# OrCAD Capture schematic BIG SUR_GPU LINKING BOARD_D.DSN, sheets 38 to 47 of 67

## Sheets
38 P38  PCIe x16 Slot-7: size C
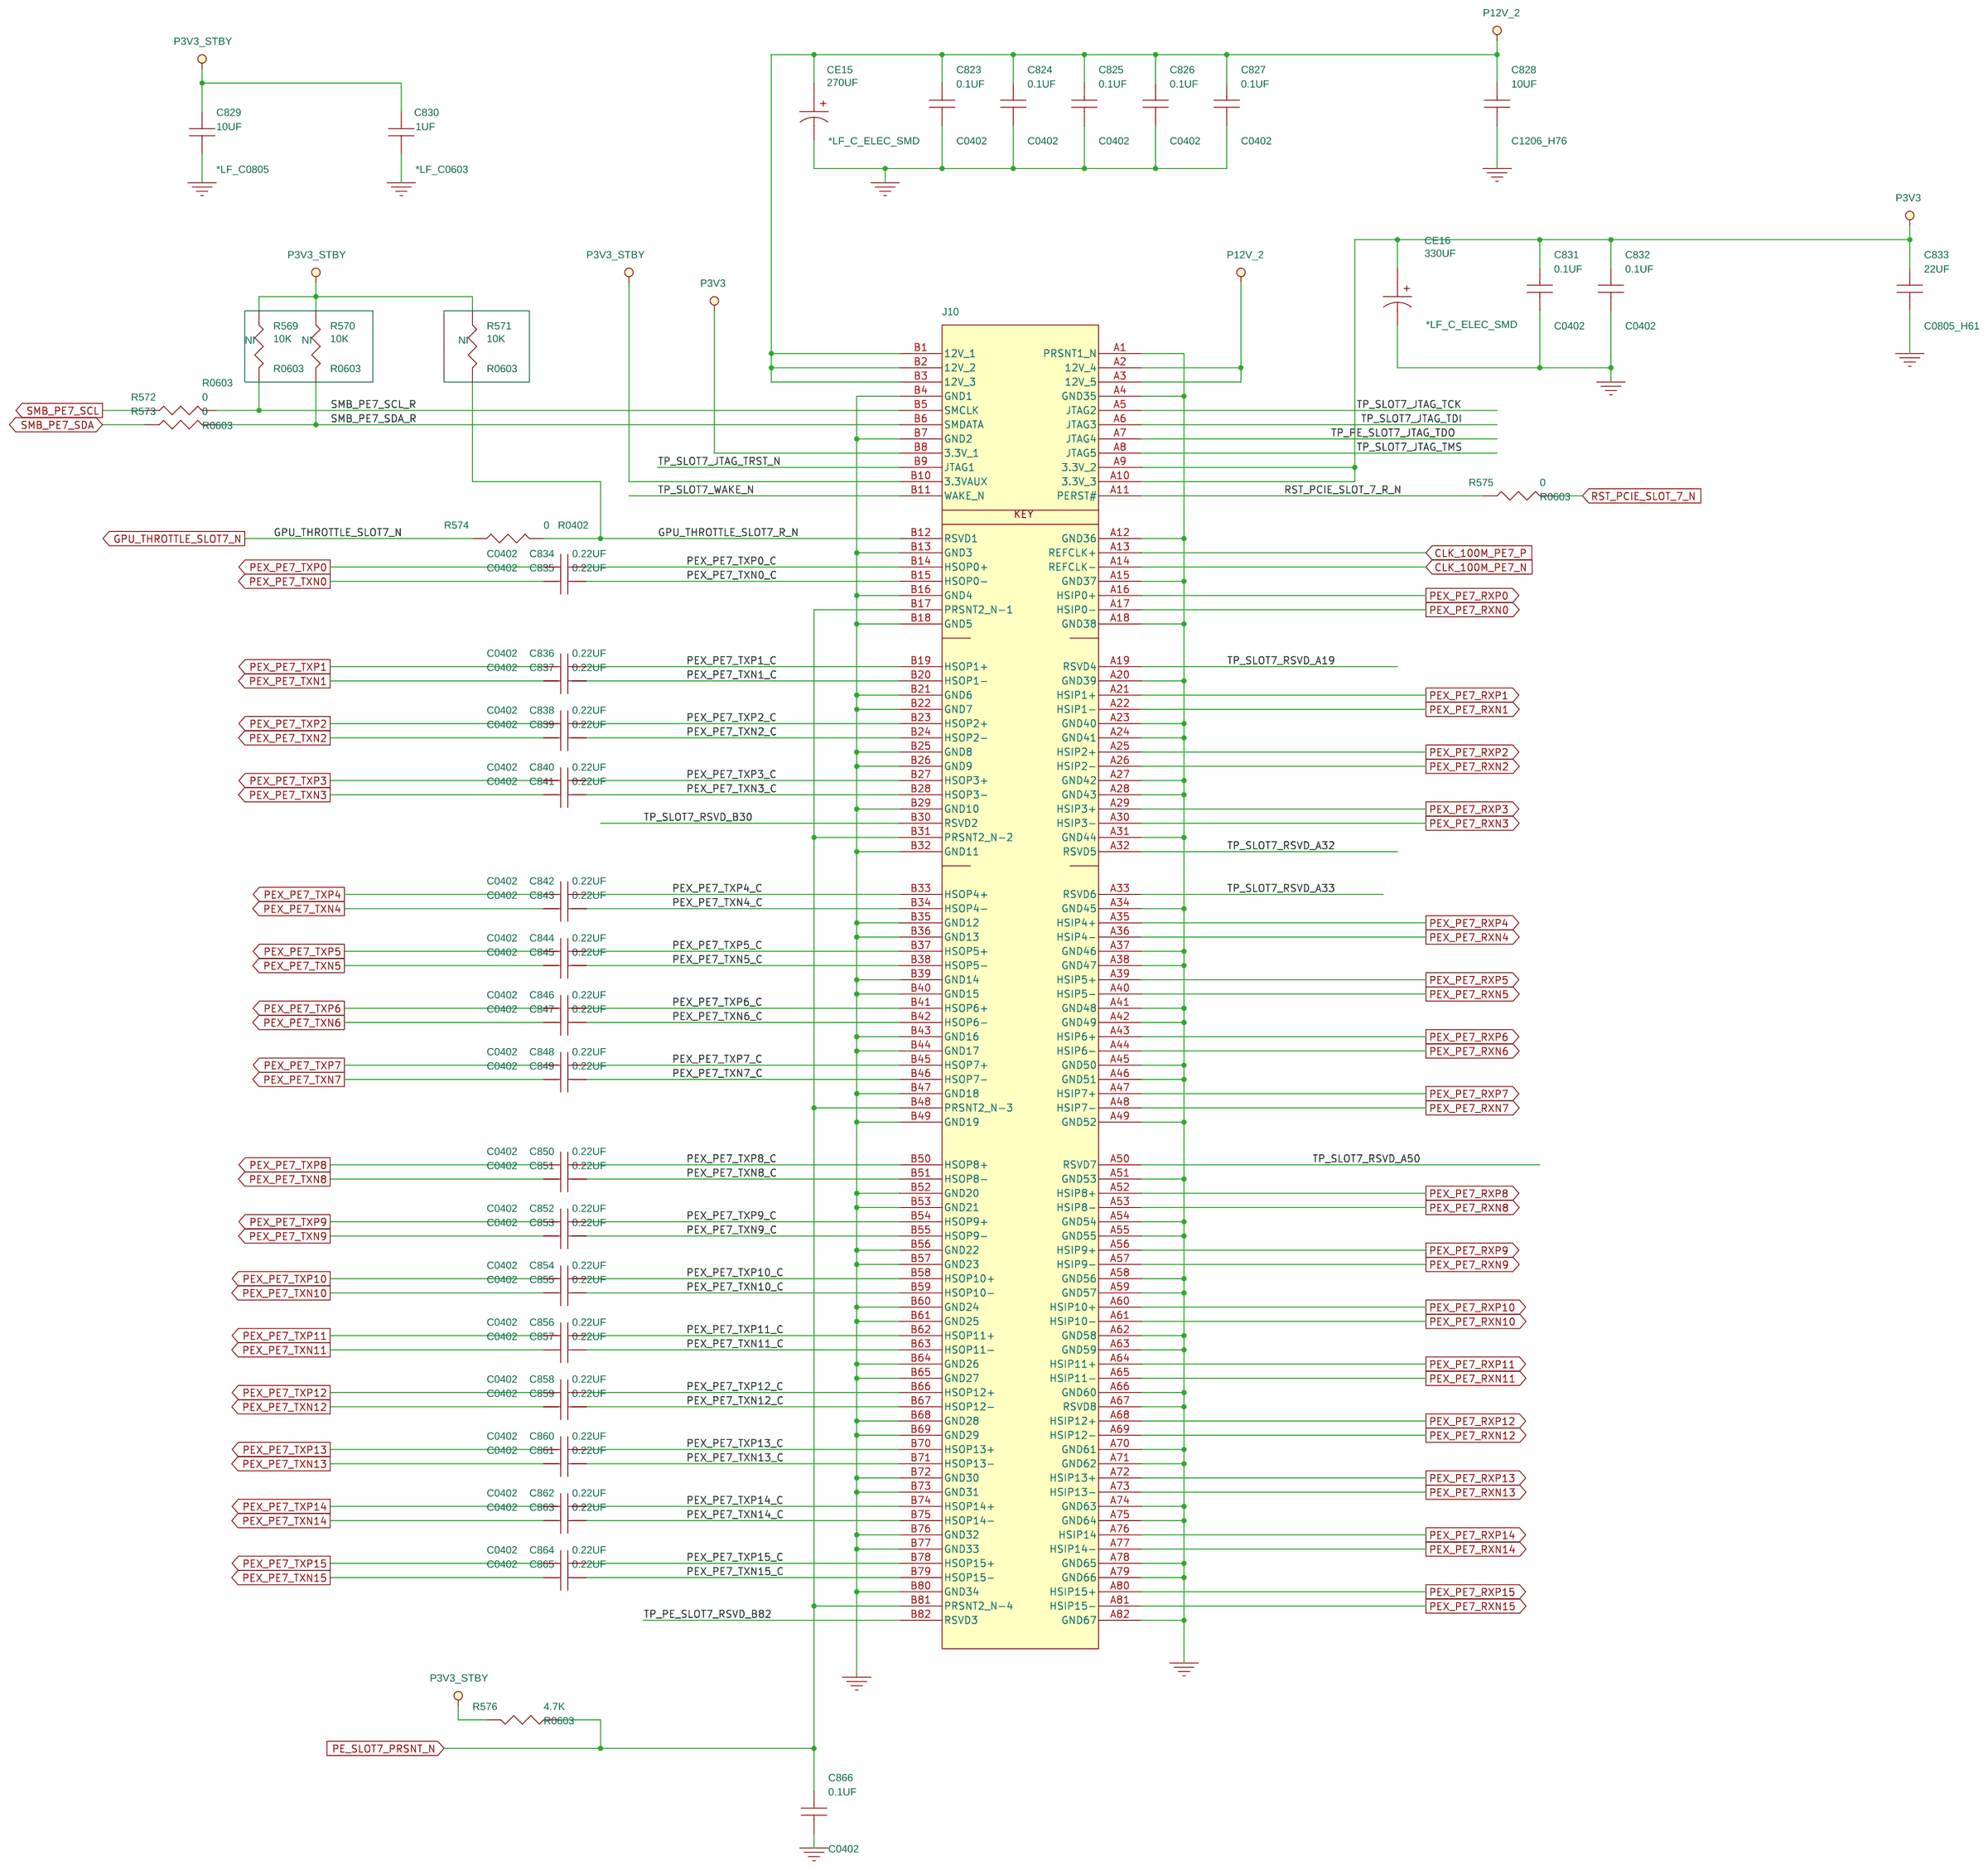
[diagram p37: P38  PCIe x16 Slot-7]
39 P39  MINI SAS HD for NIC 1&2: size C
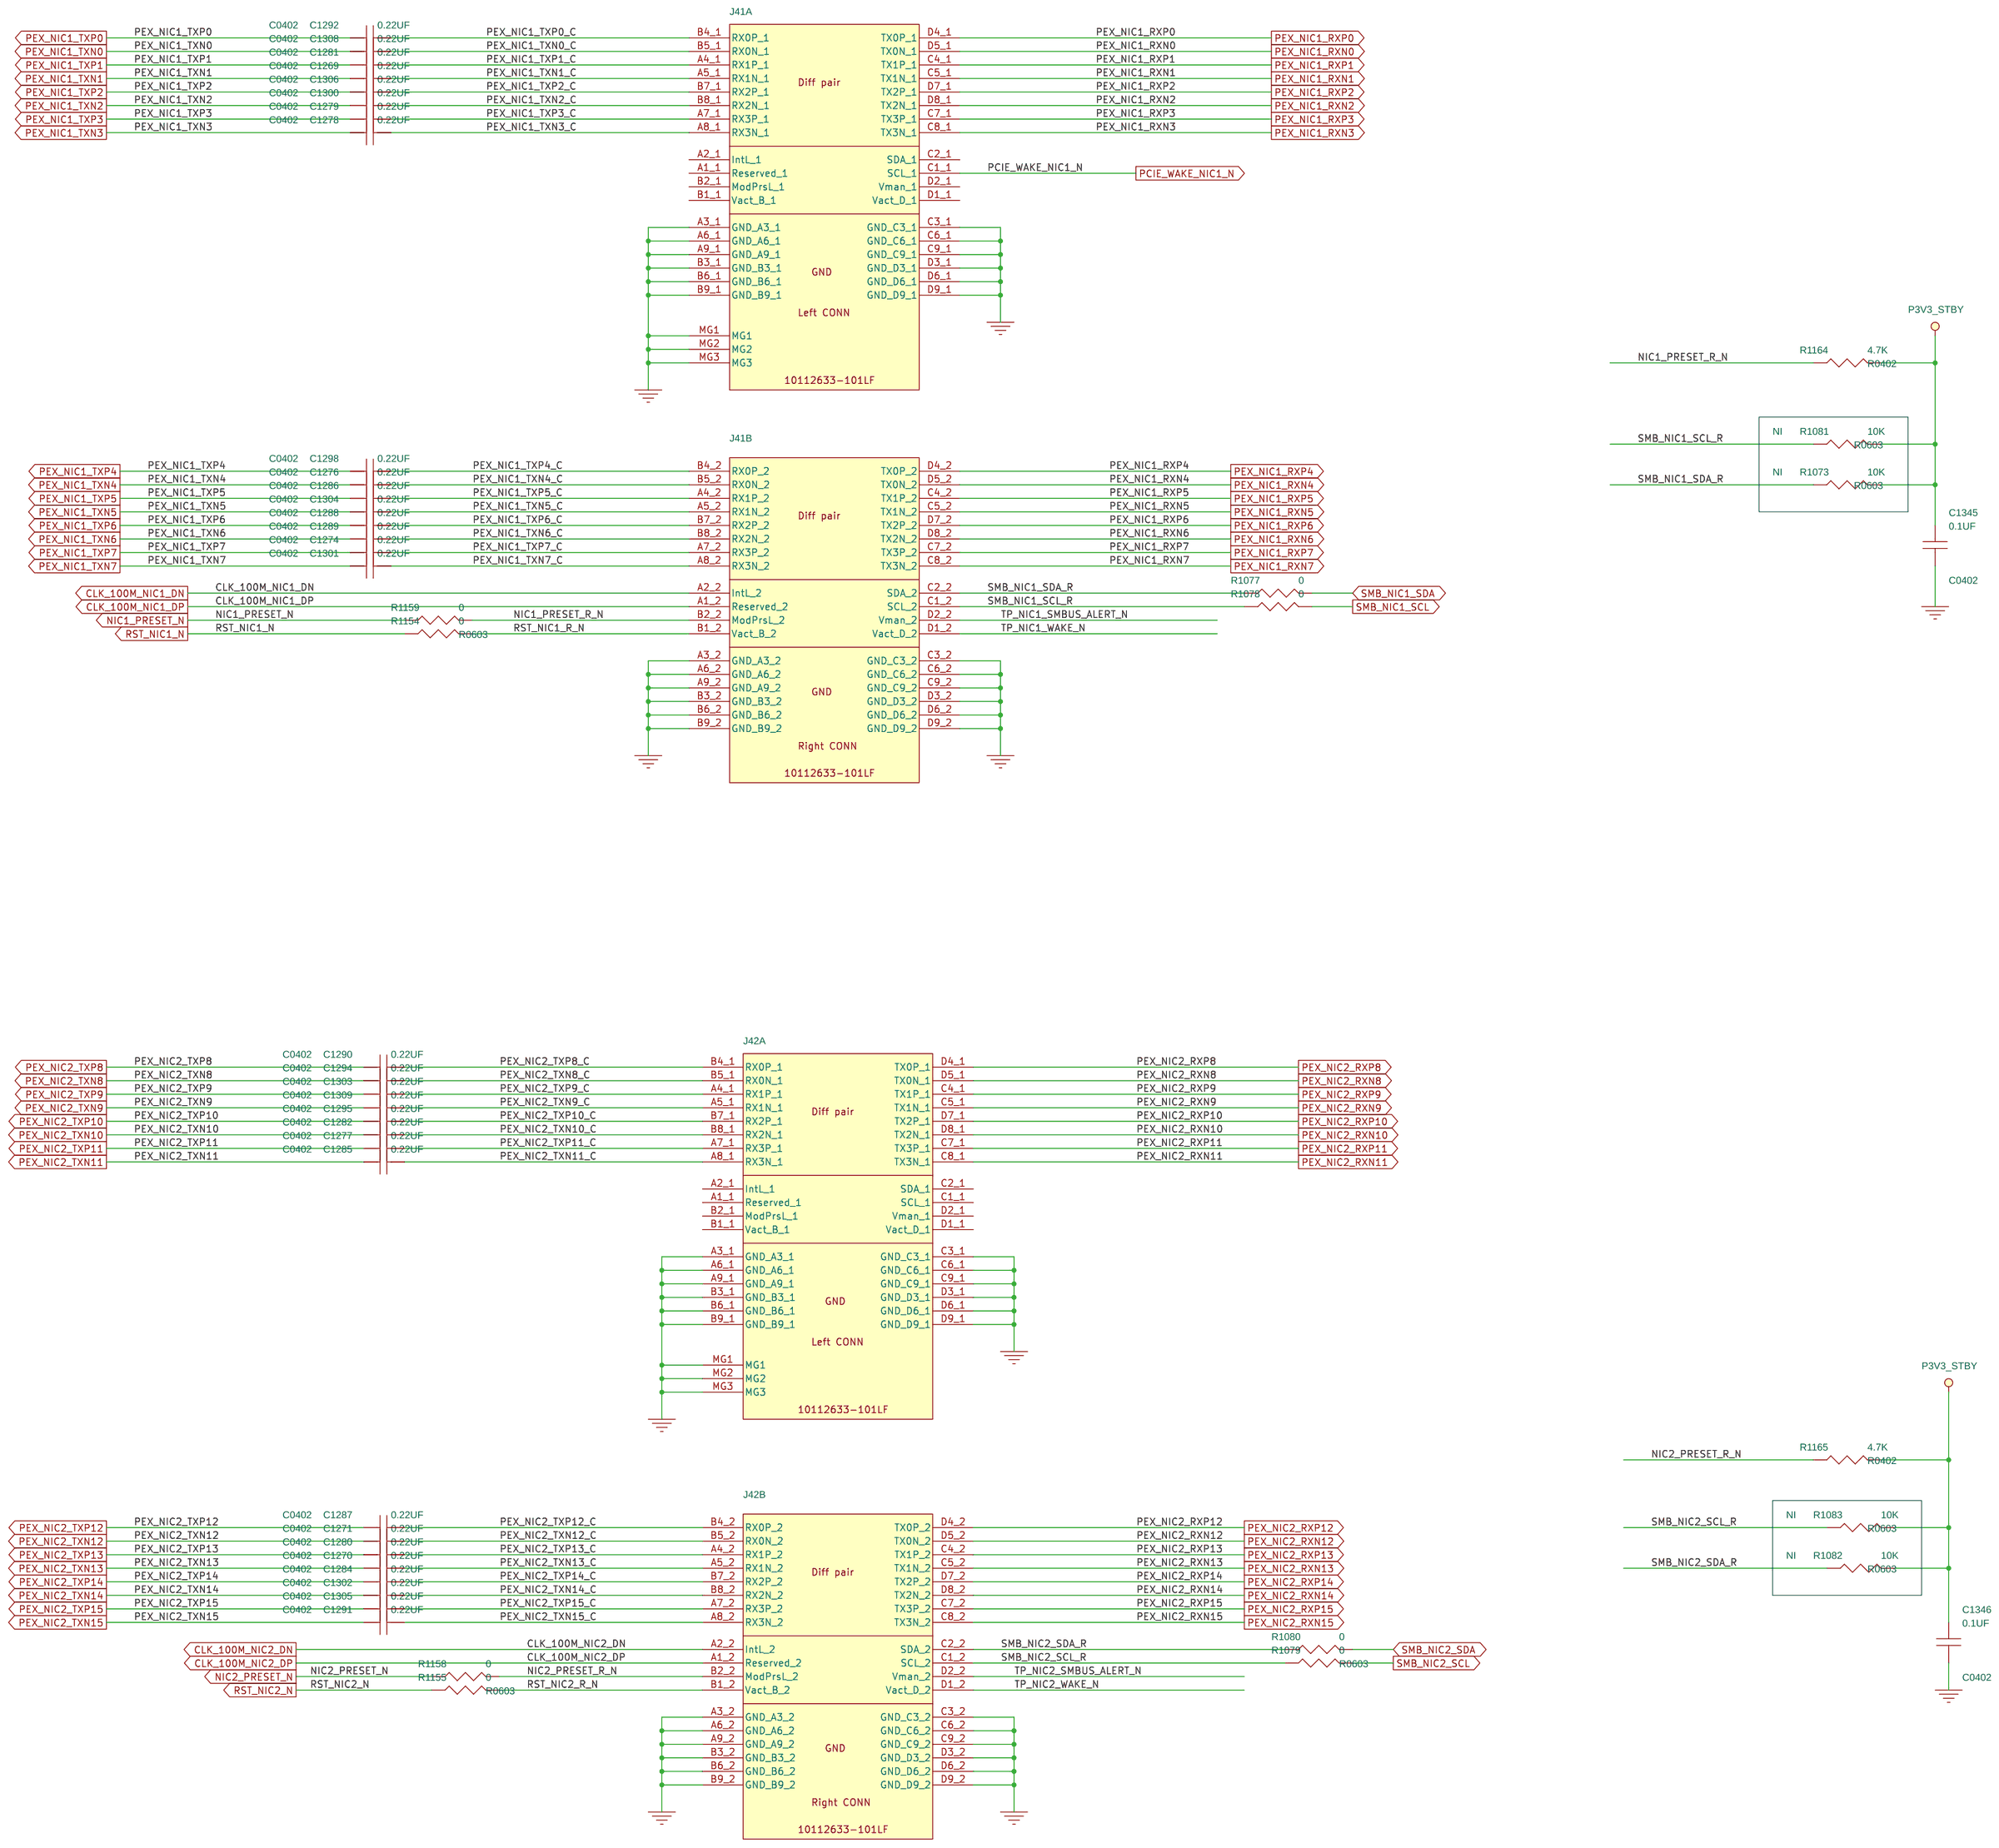
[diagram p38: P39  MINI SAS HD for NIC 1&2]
40 P40  MINI SAS HD for NIC 3&4: size C
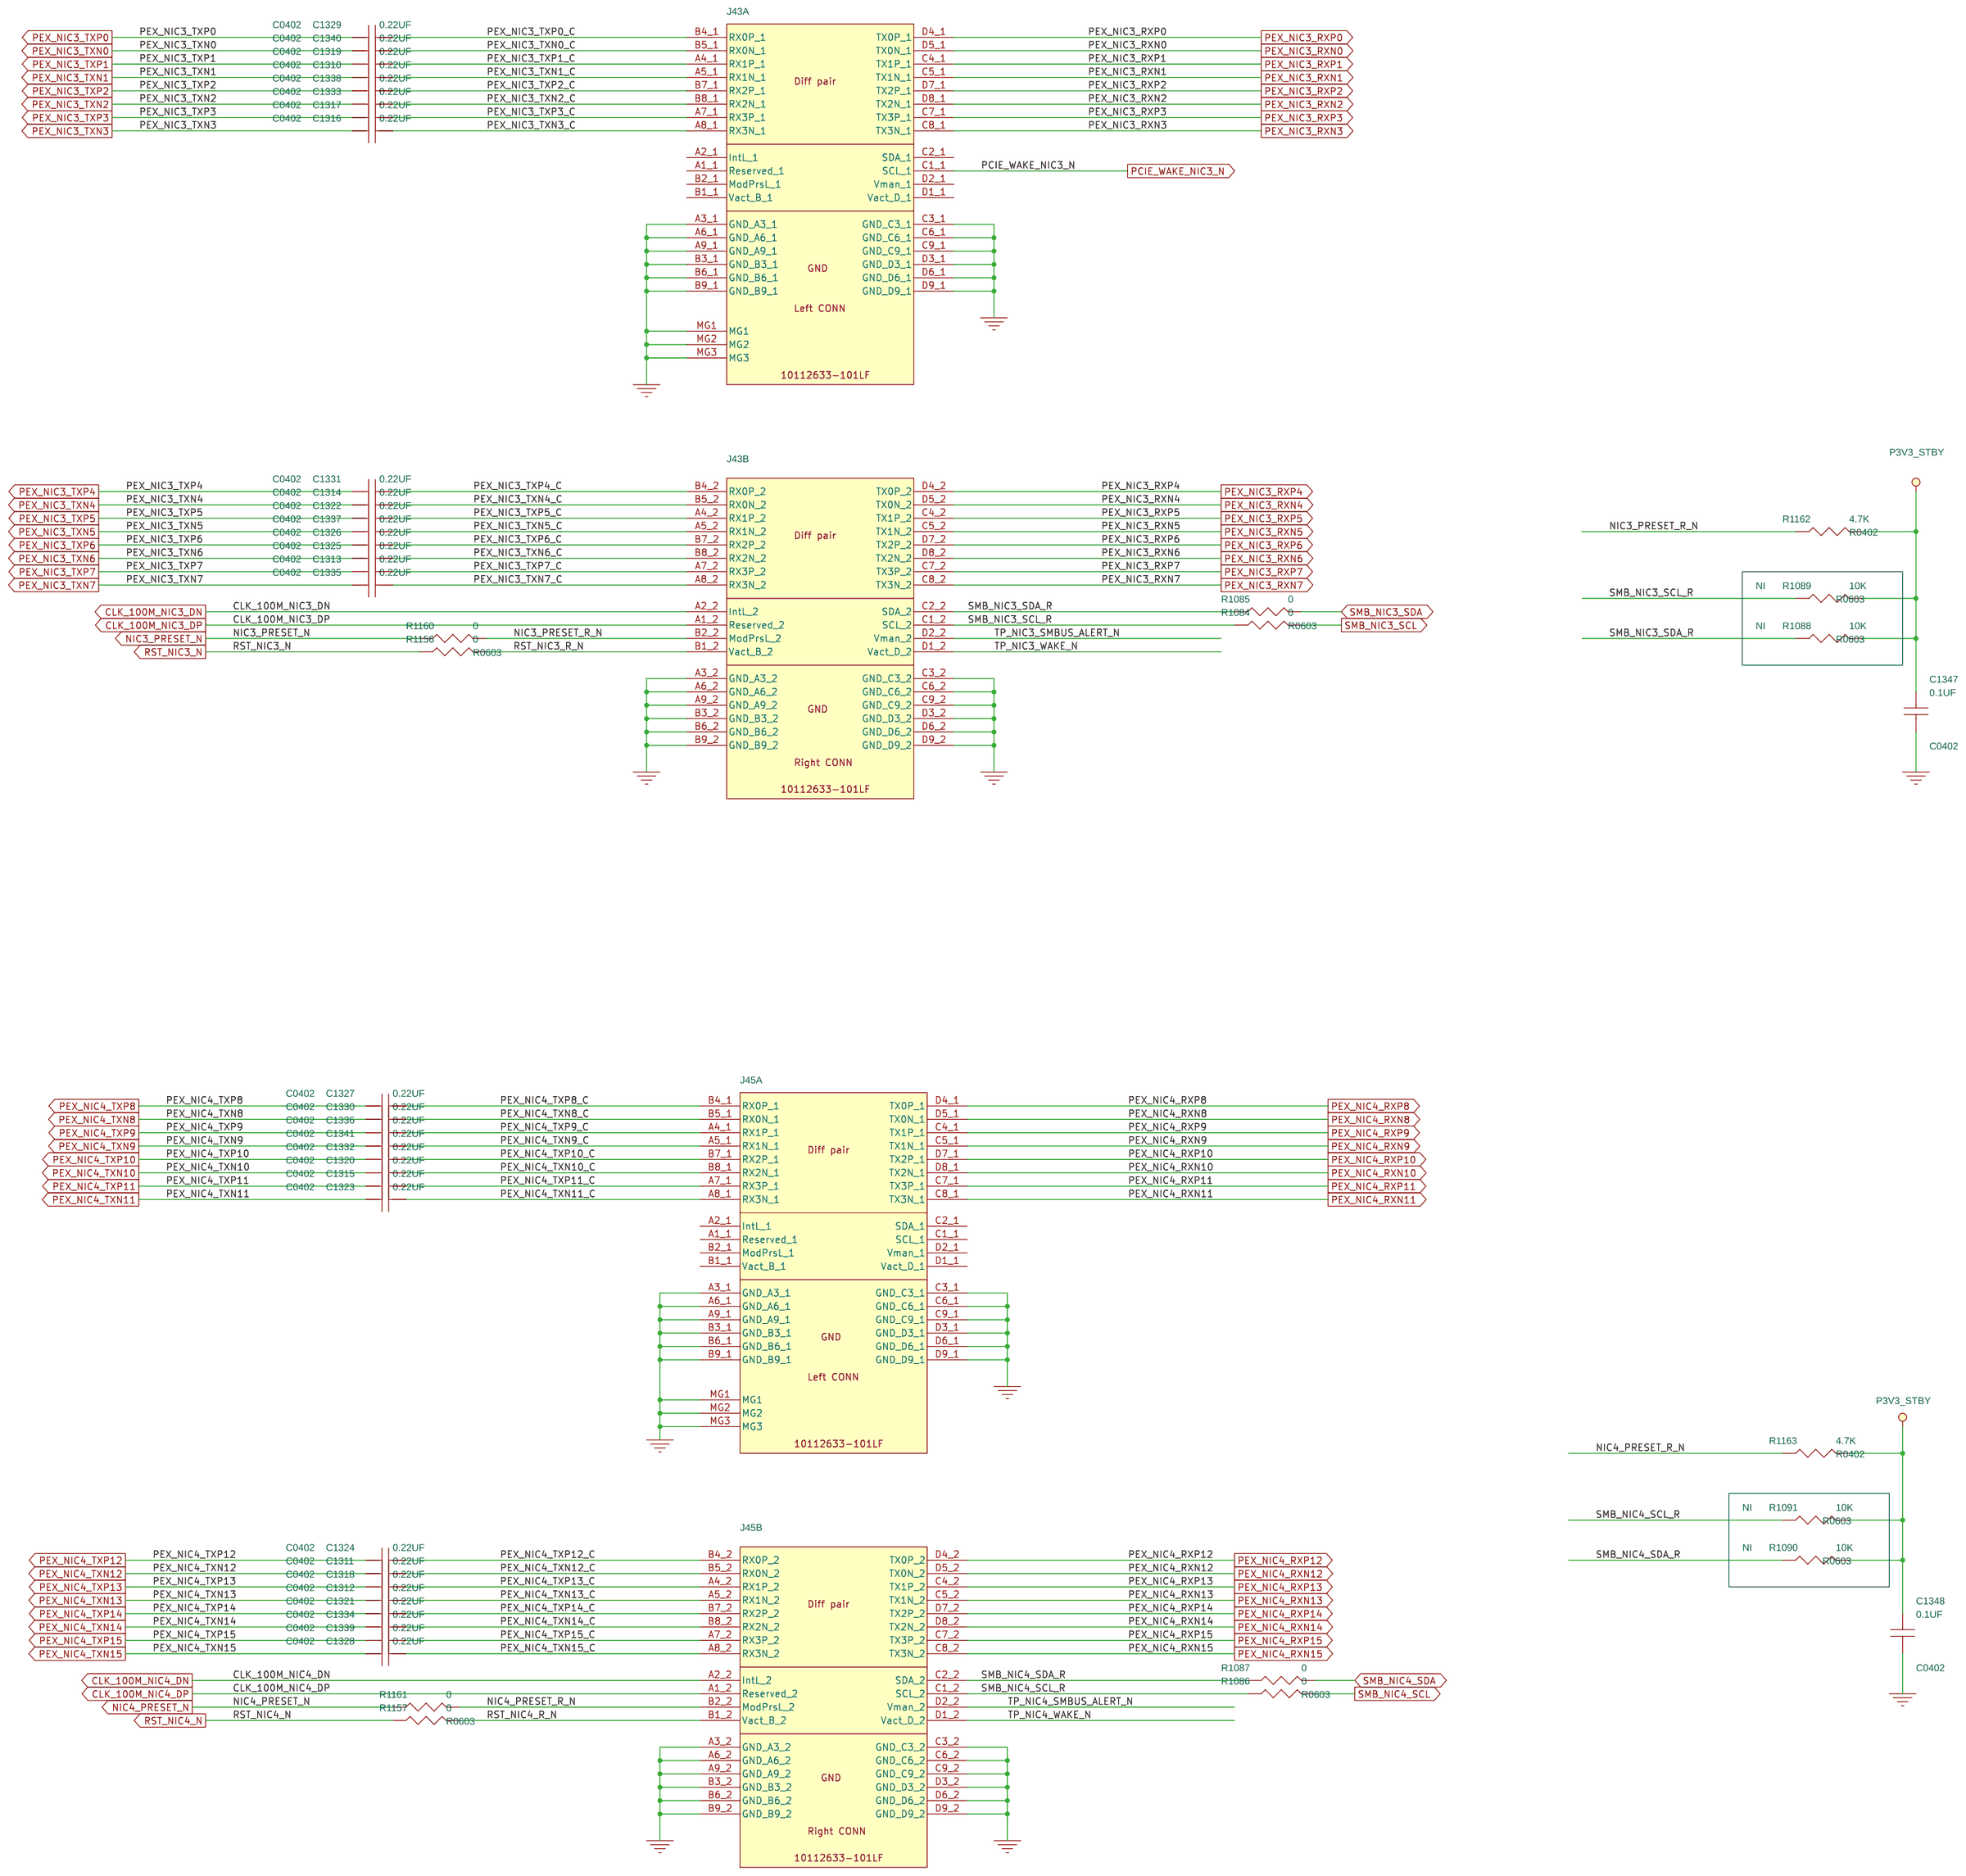
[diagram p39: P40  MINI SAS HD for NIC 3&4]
41 P41  Main Board Power Connector: size C
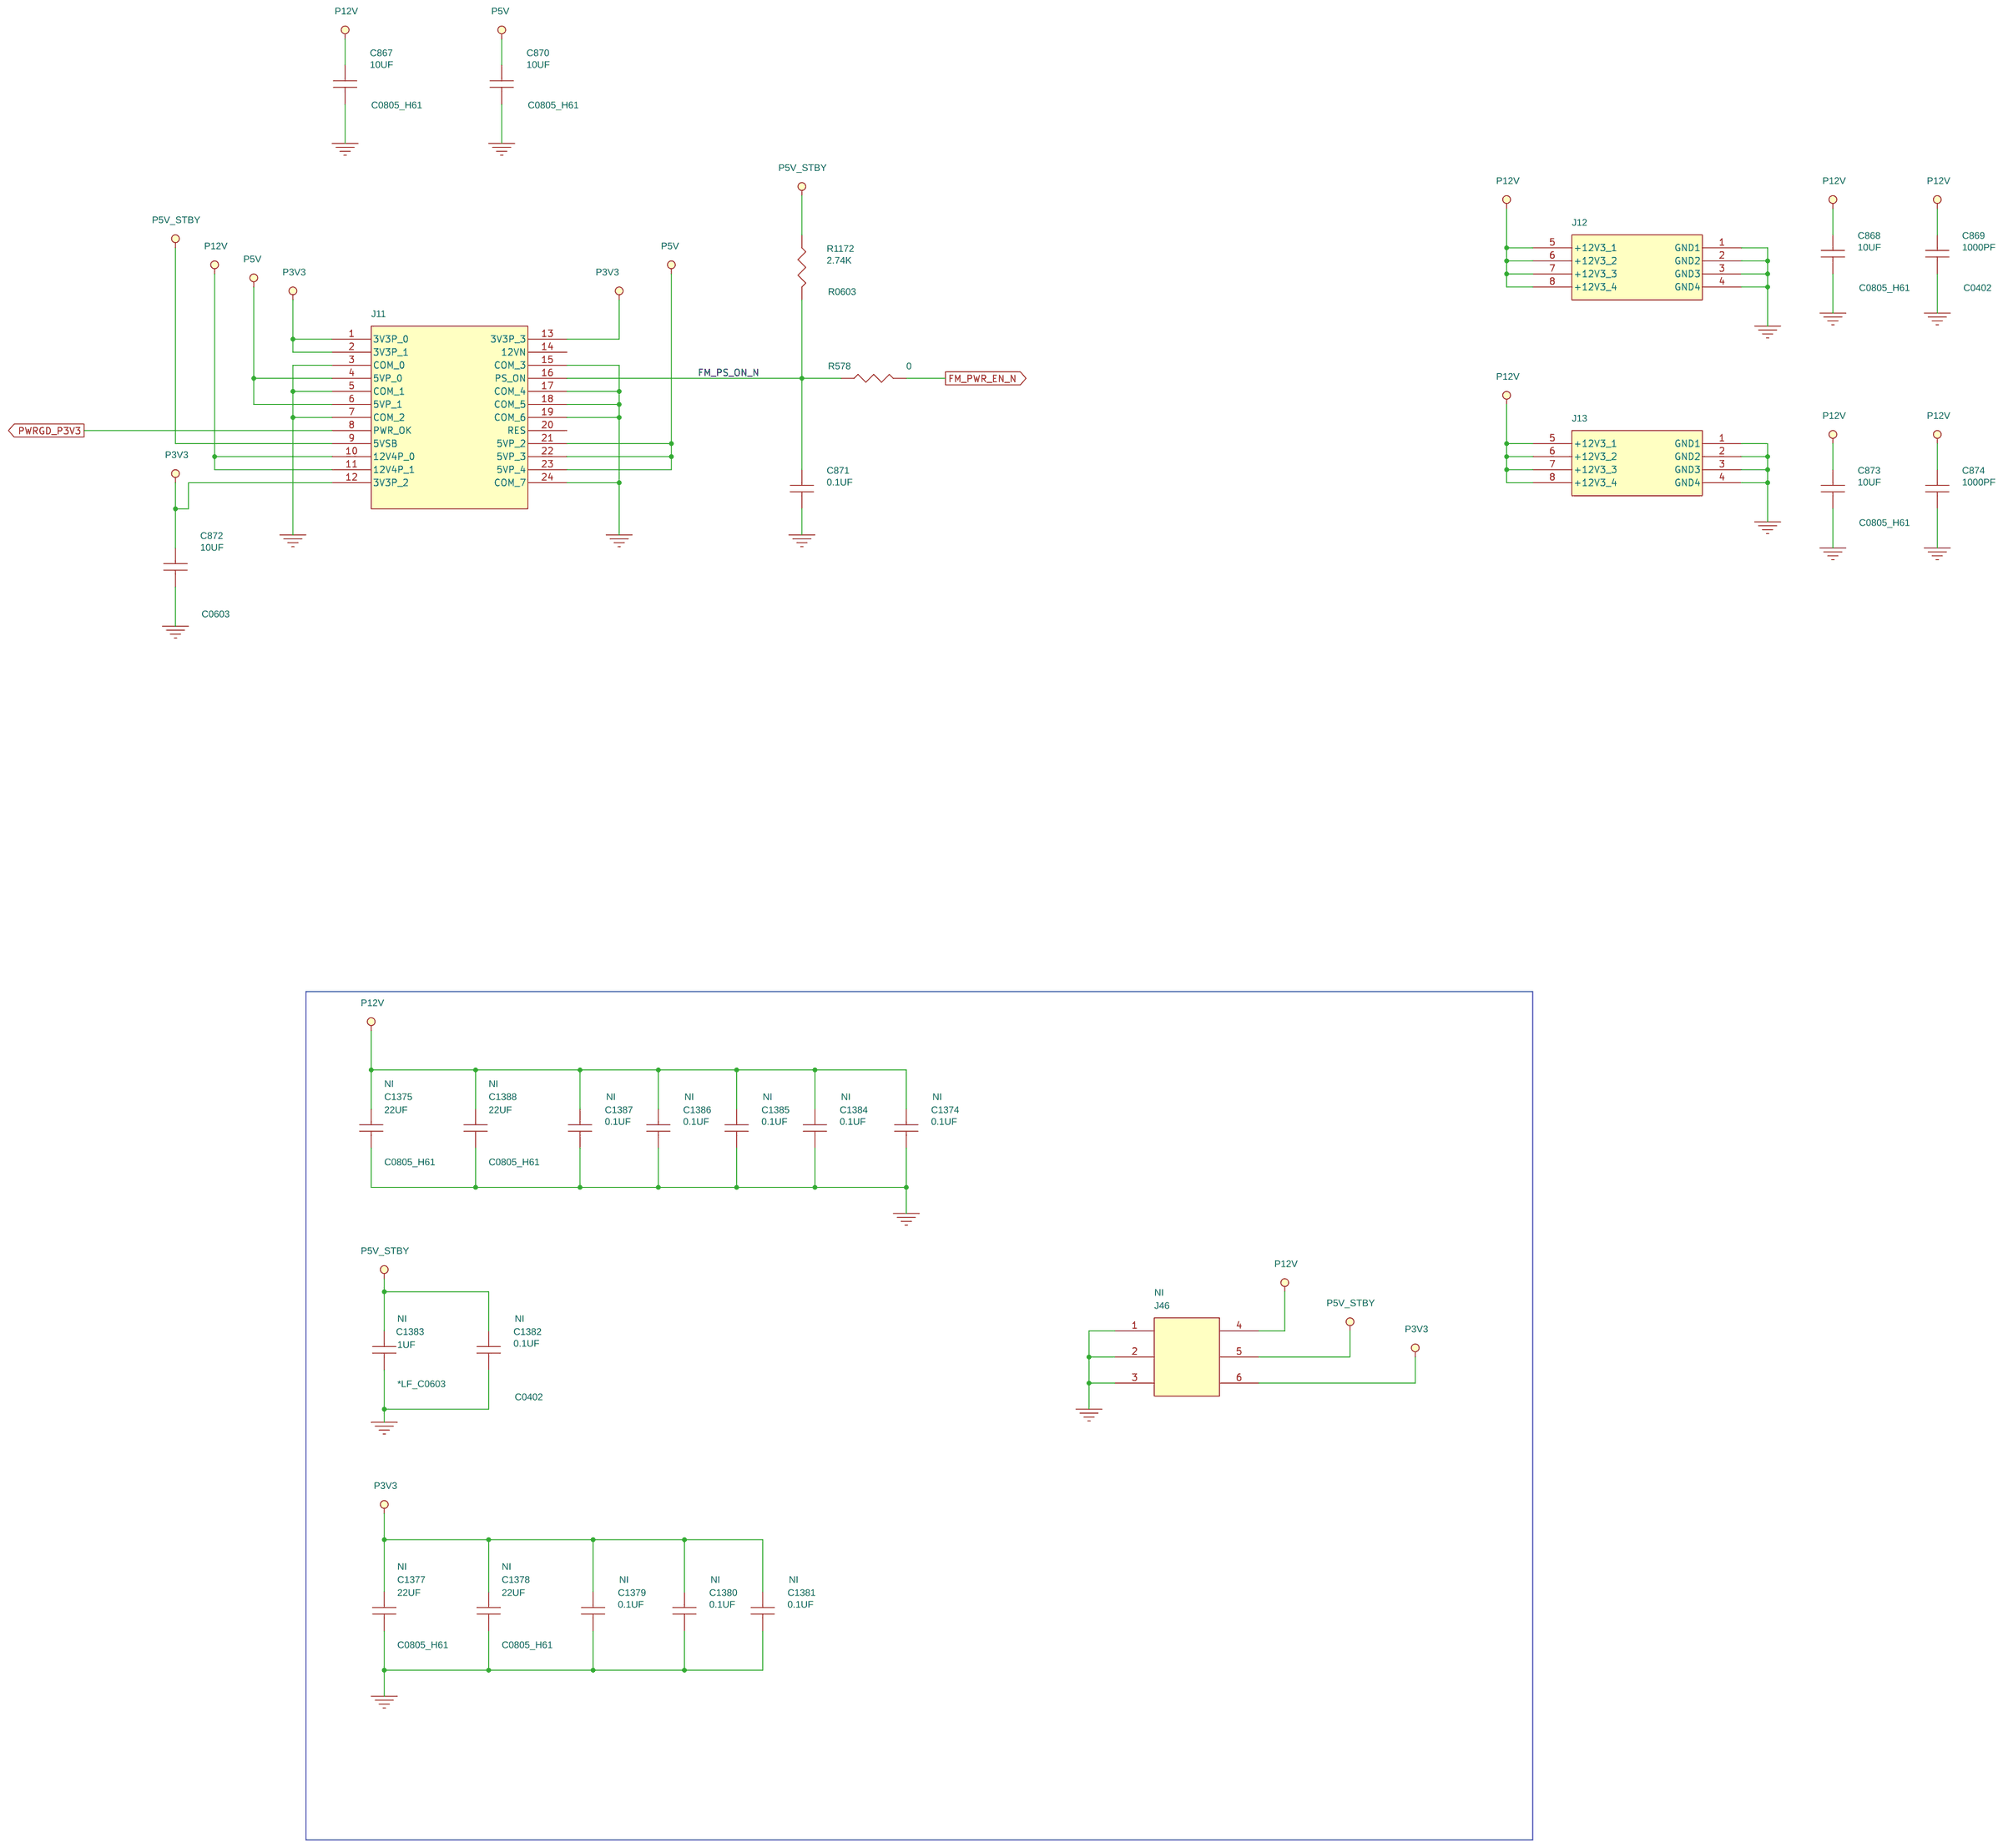
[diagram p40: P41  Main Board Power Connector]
42 P42  PCIe Power Connector: size C
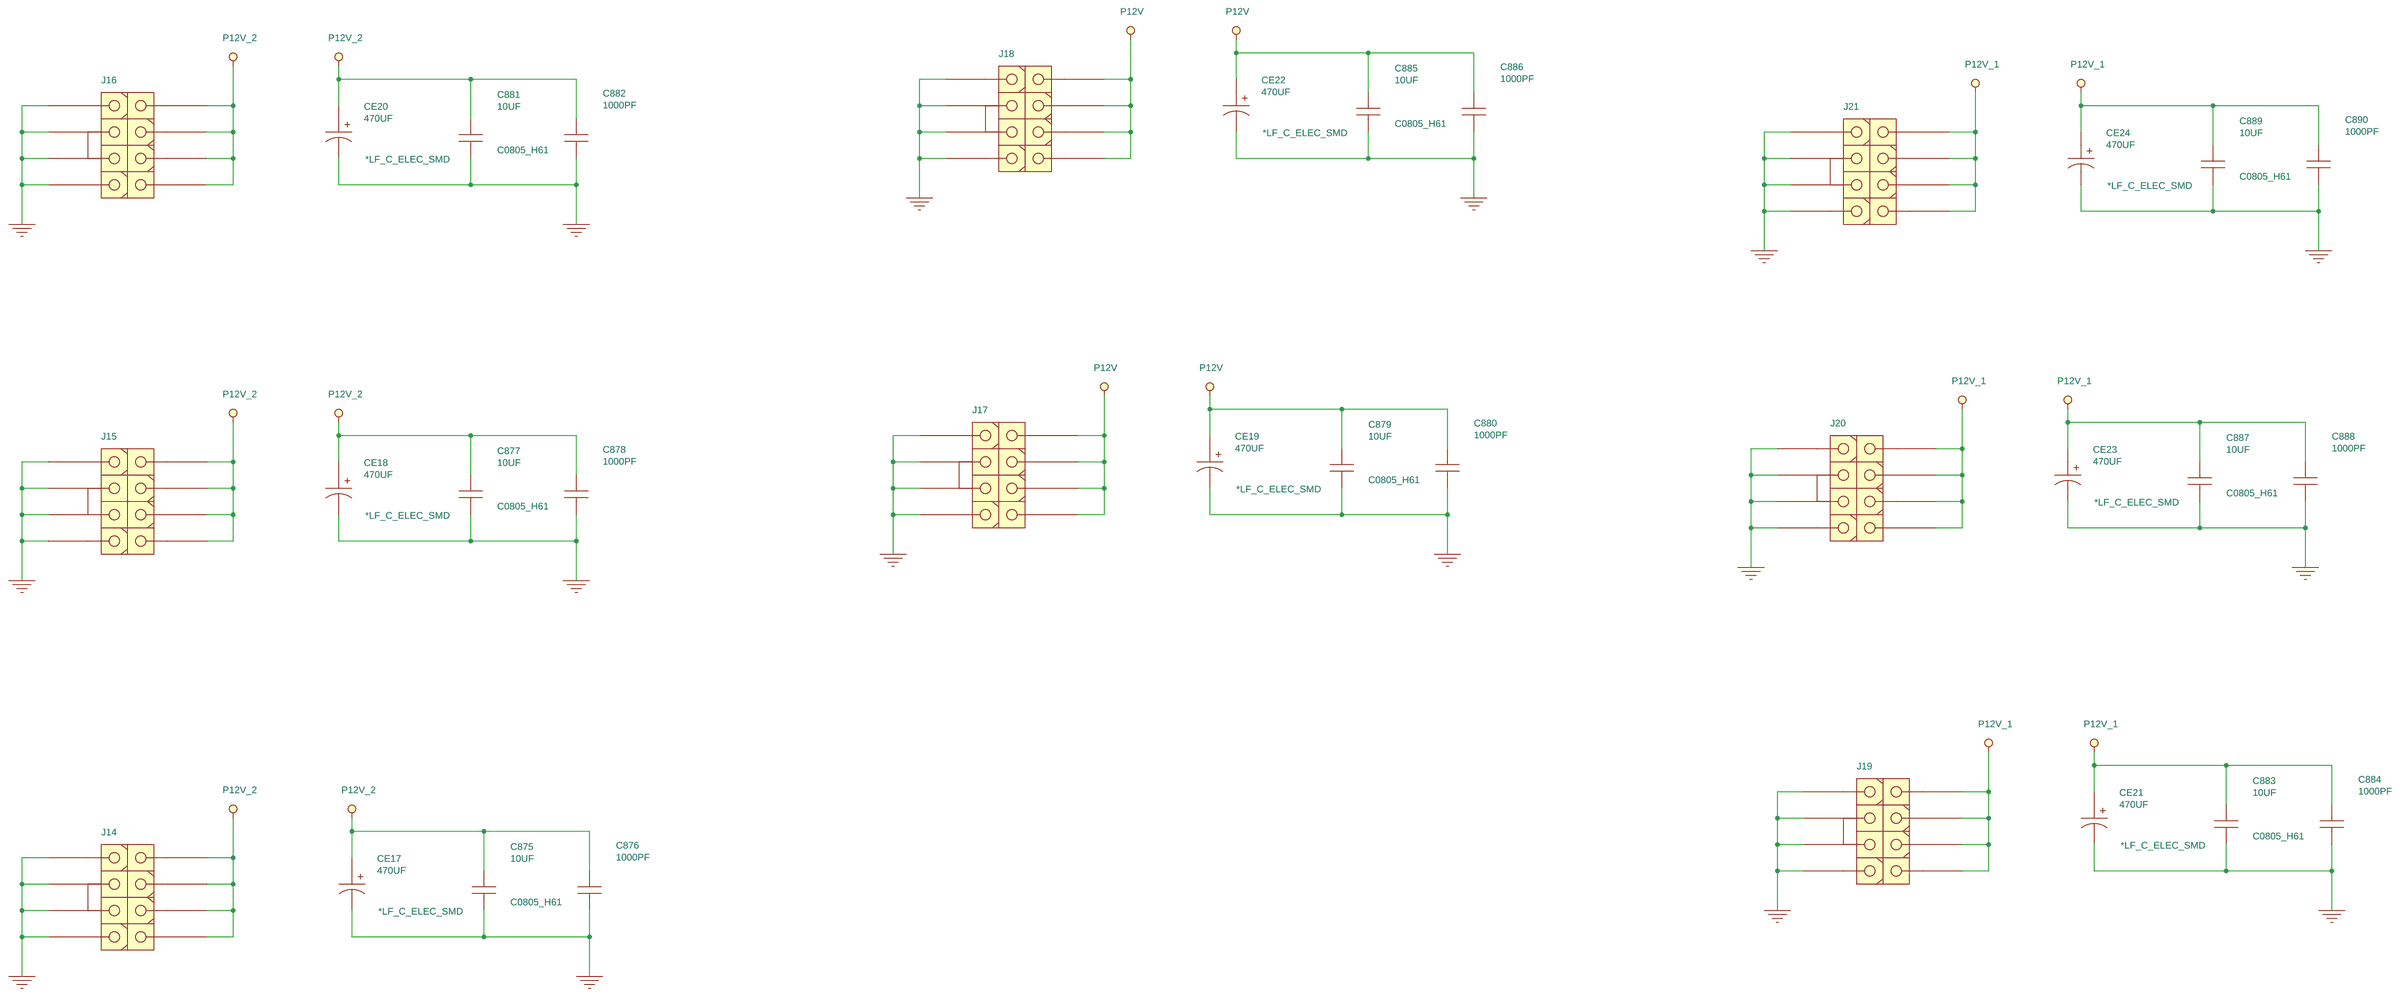
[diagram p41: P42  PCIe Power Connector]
43 P44  FRU & Temperature Sensor: size C
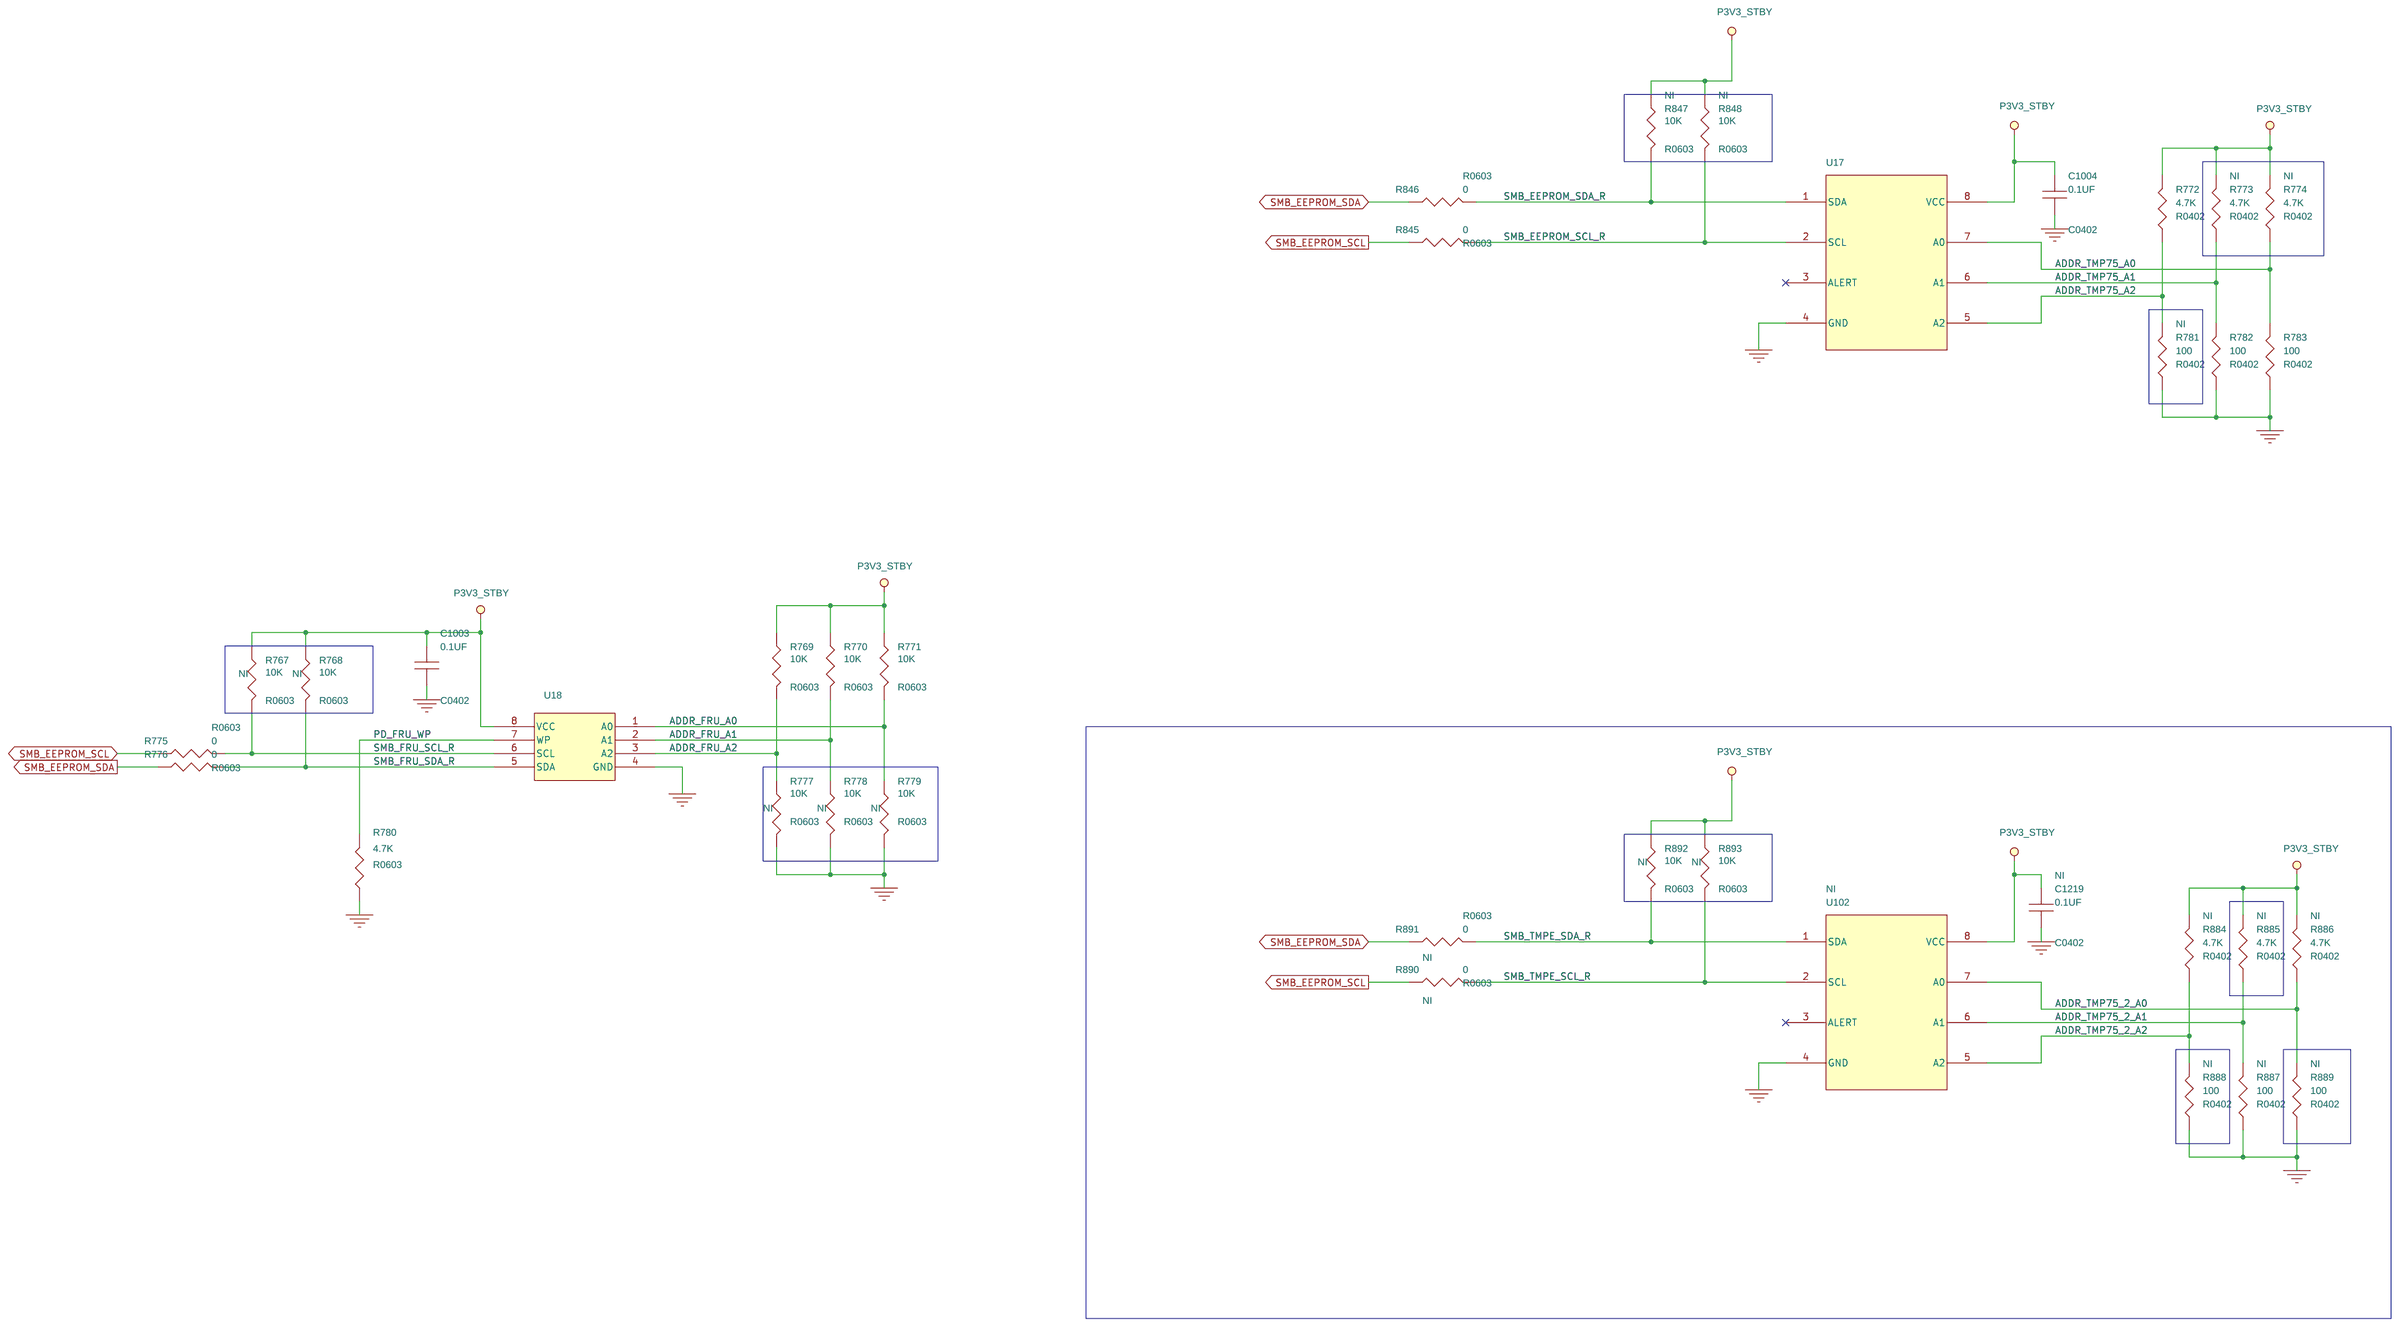
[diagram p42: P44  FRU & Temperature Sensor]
44 P45  SMBus & PMBus Connector: size C
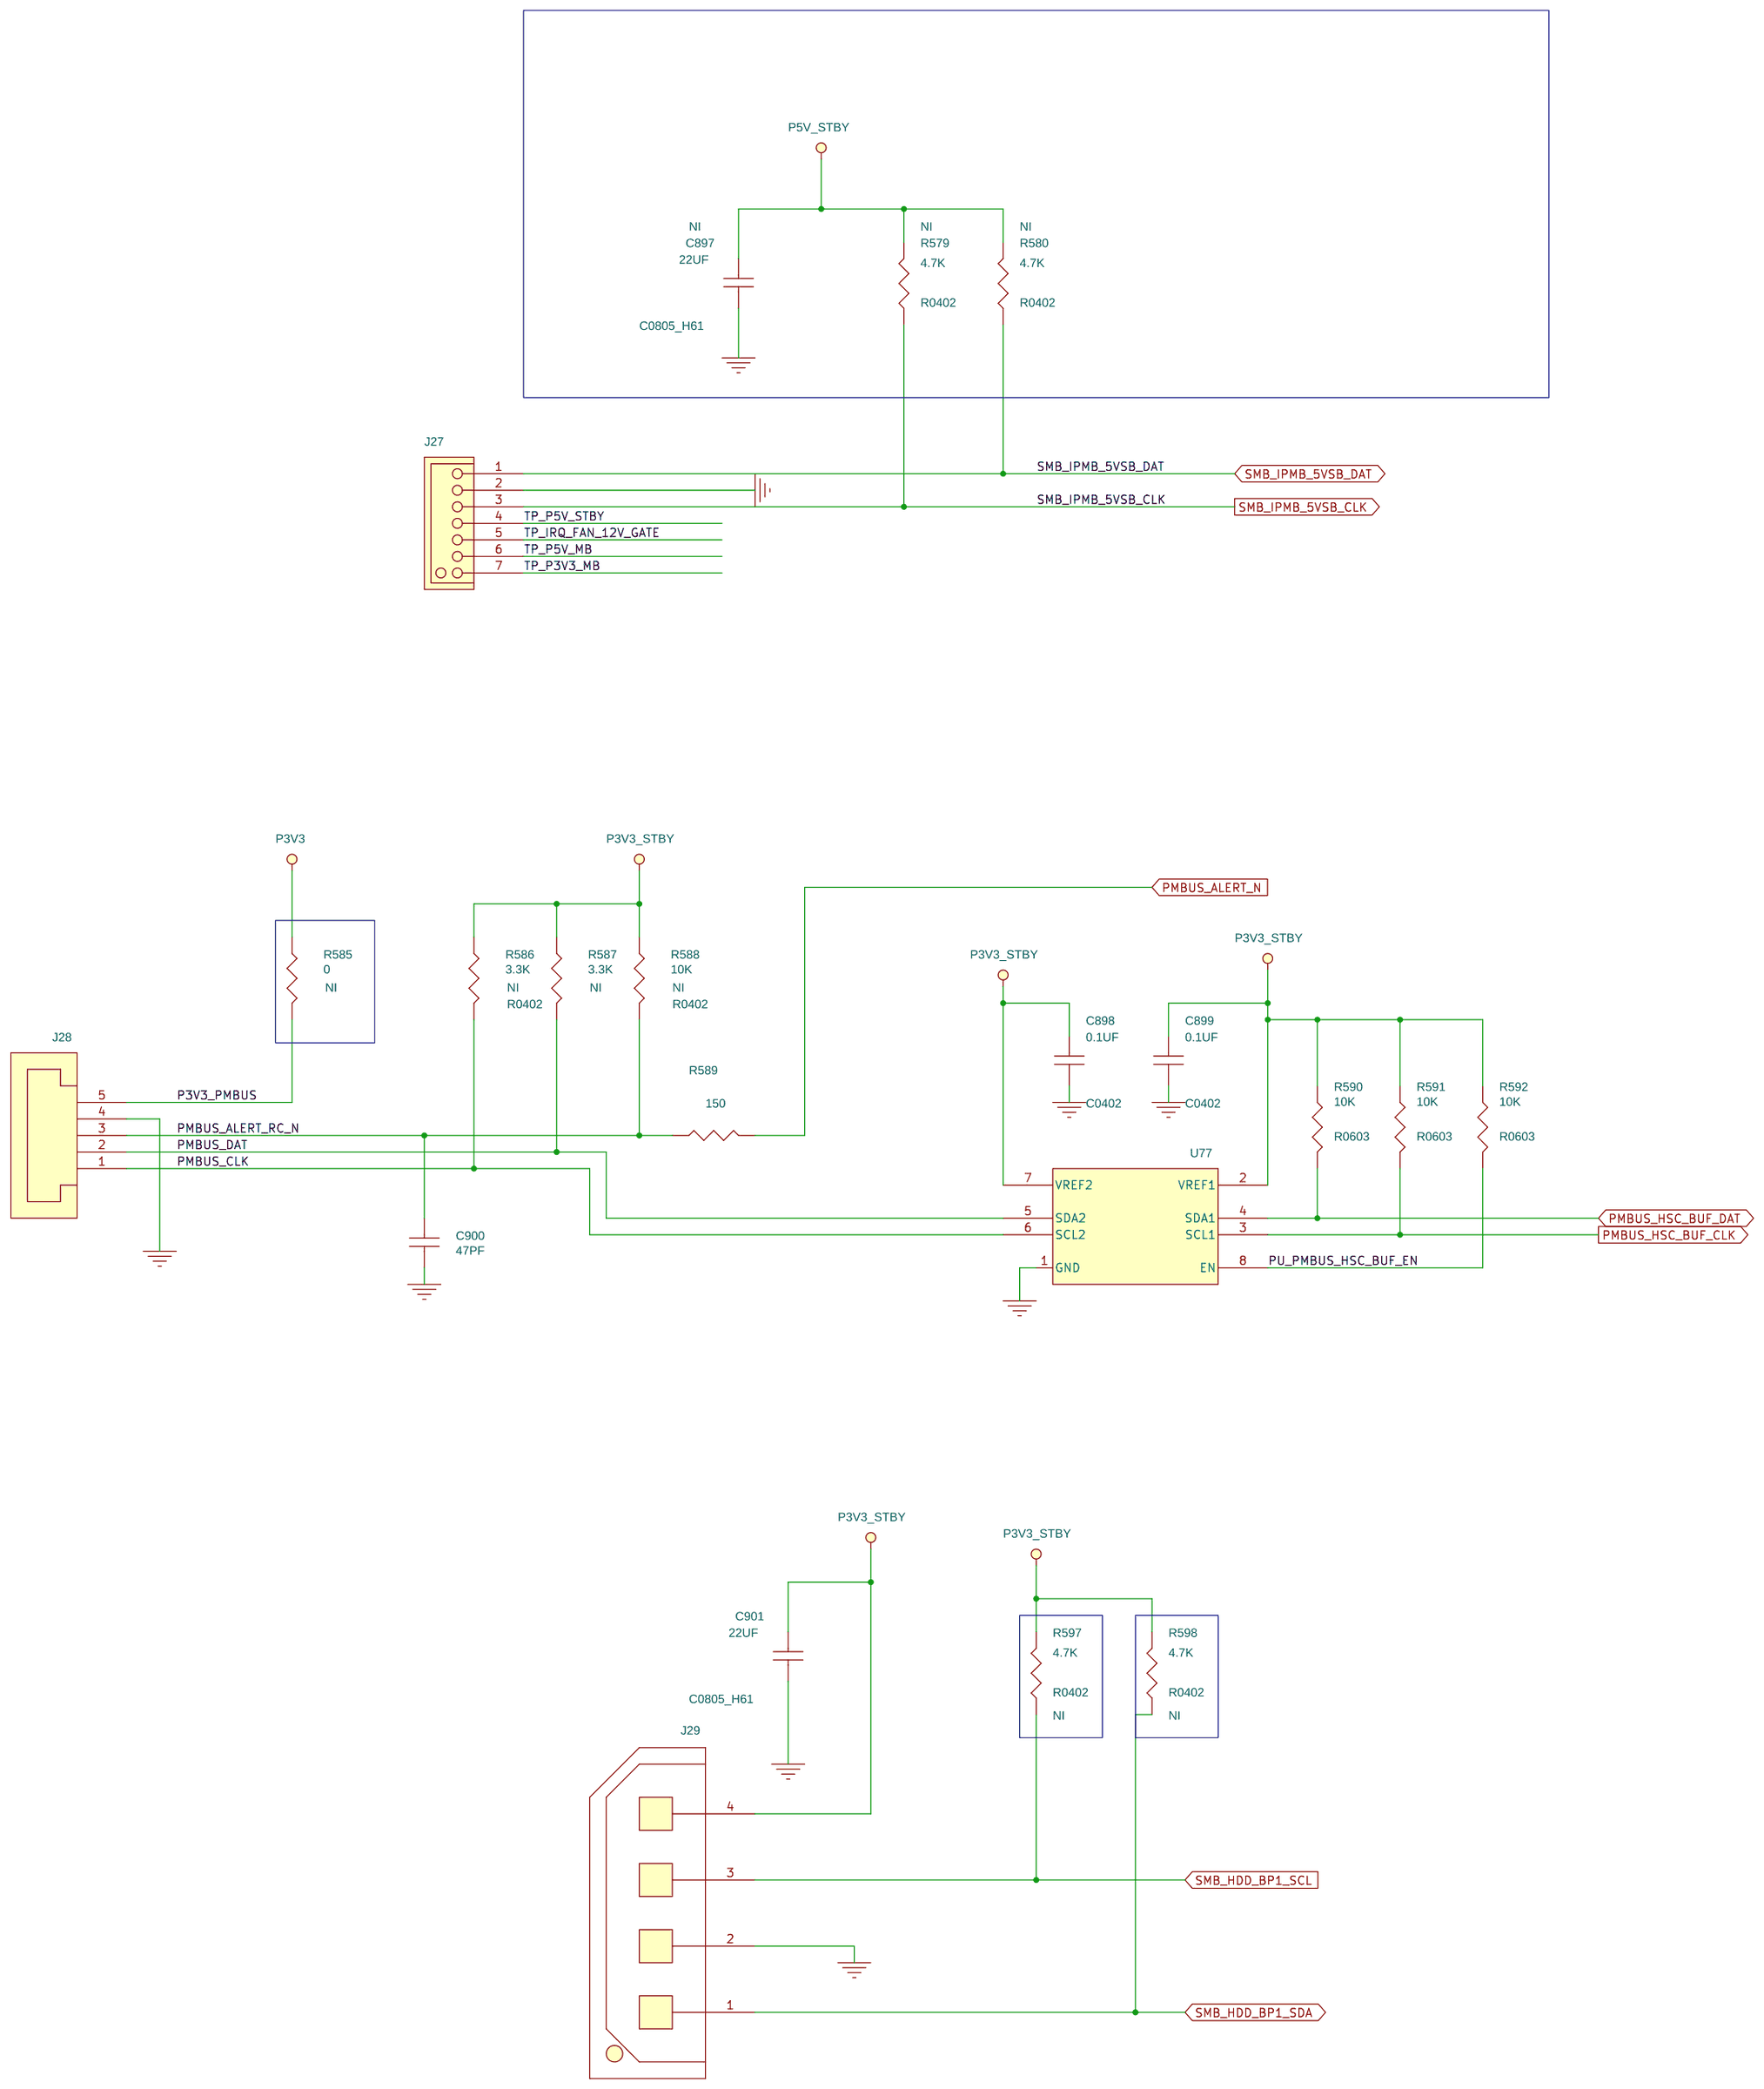
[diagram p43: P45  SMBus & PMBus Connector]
45 P46  SMBus Multiplexer: size C
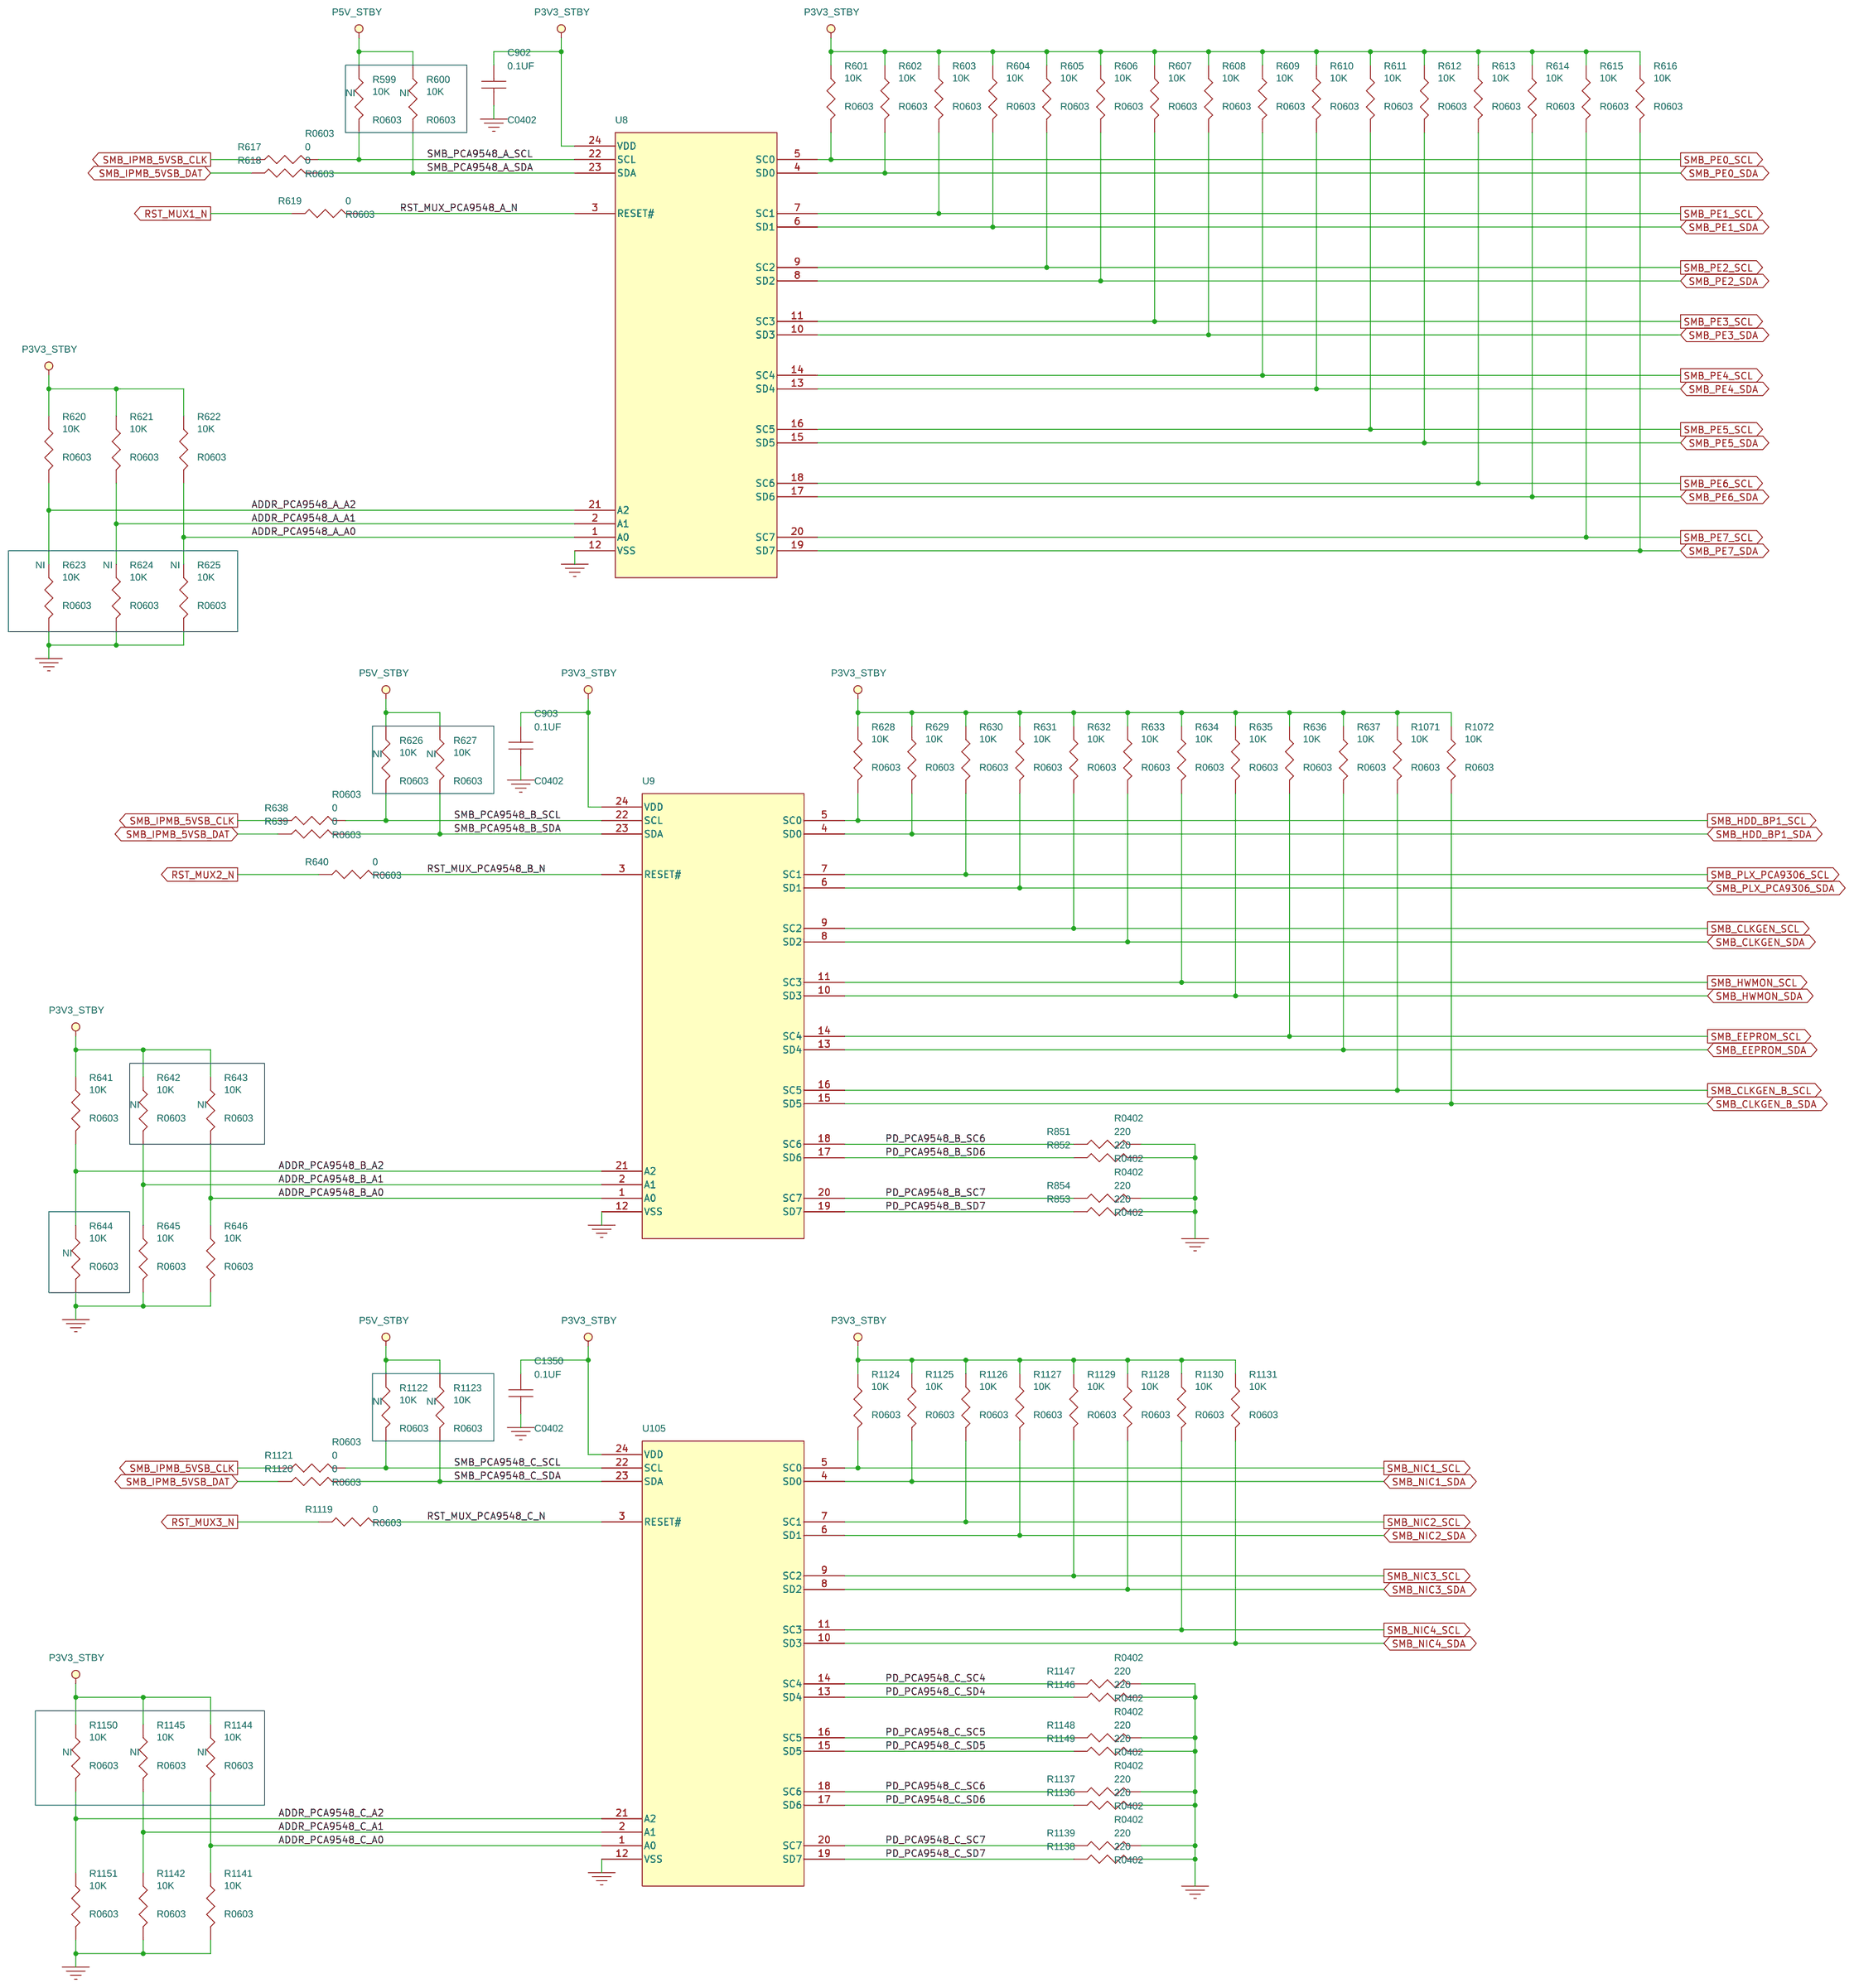
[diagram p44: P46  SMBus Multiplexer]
46 P47  PLX I2C Debug Header: size B
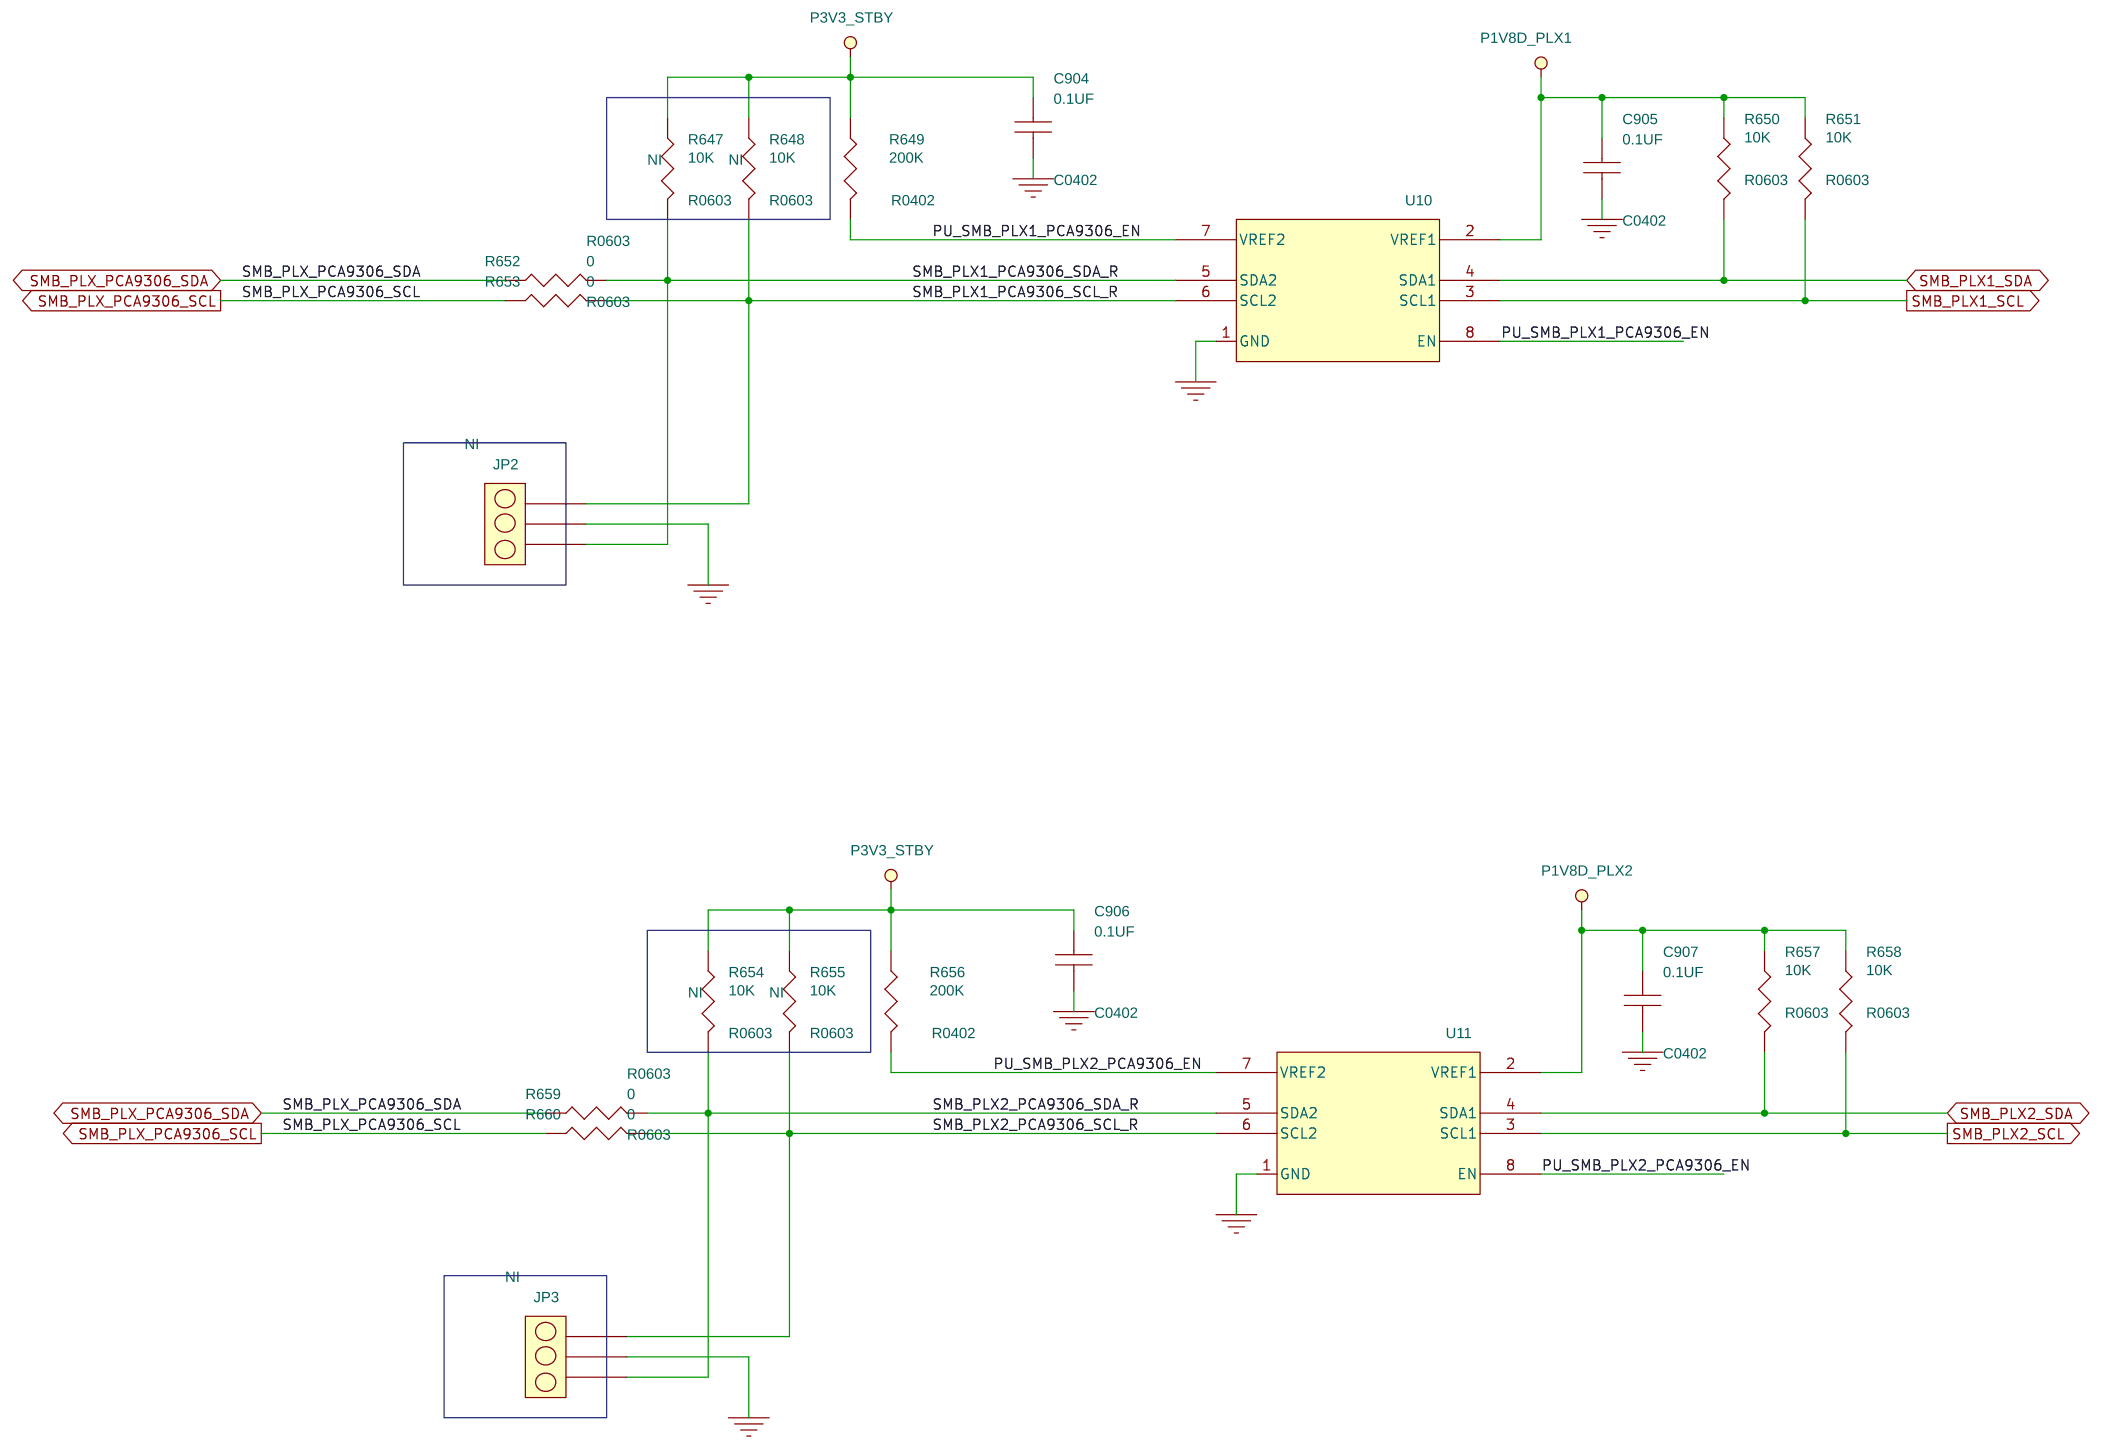
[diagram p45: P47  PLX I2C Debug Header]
47 P48  P12V_STBY Hot Swap: size Custom
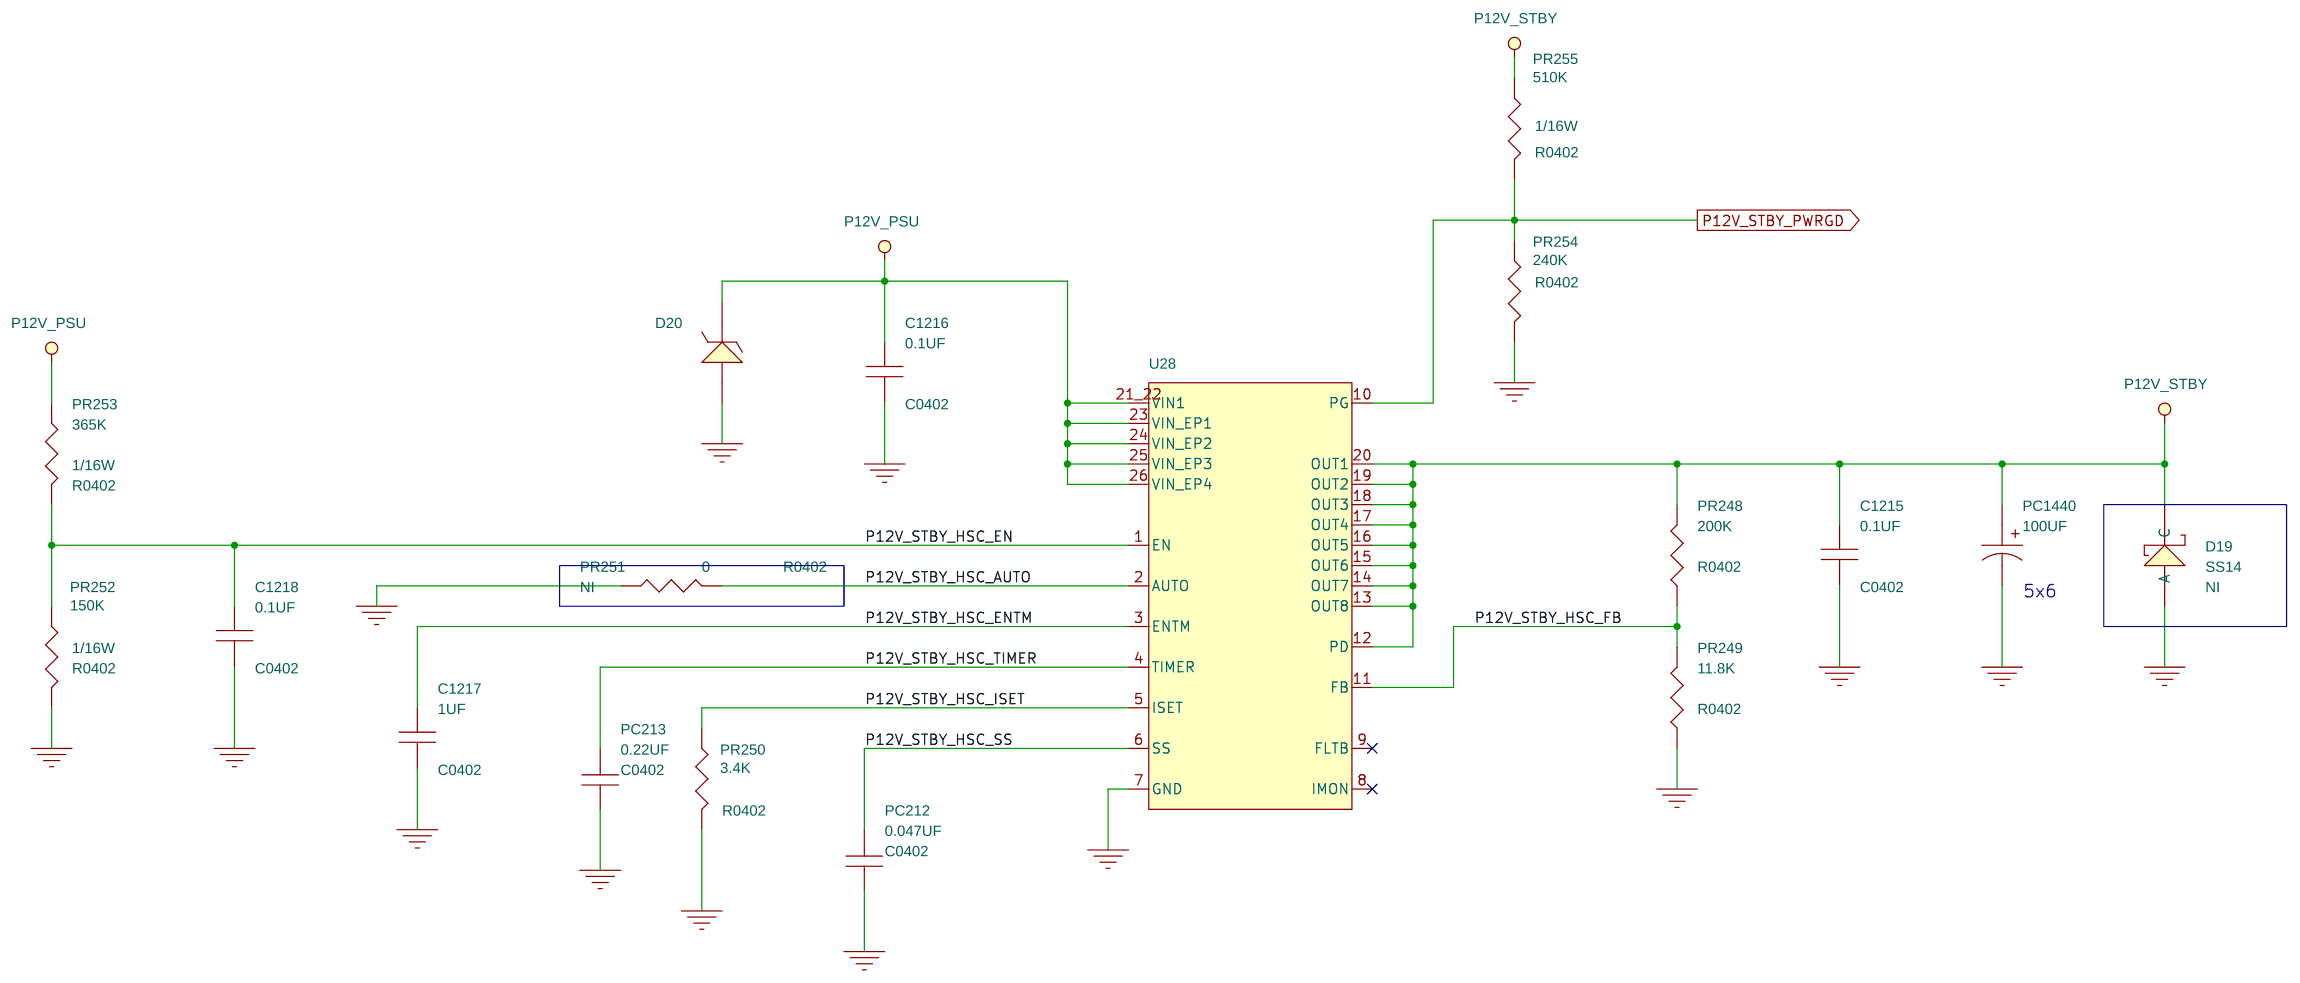
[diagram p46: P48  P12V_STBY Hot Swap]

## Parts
sheet P38  PCIe x16 Slot-7
C823  0.1UF  [C0402]
C824  0.1UF  [C0402]
C825  0.1UF  [C0402]
C826  0.1UF  [C0402]
C827  0.1UF  [C0402]
C828  10UF  [C1206_H76]
C829  10UF  [C0805_H61]
C830  1UF  [C0603]
C831  0.1UF  [C0402]
C832  0.1UF  [C0402]
C833  22UF  [C0805_H61]
C834  0.22UF  [C0402]
C835  0.22UF  [C0402]
C836  0.22UF  [C0402]
C837  0.22UF  [C0402]
C838  0.22UF  [C0402]
C839  0.22UF  [C0402]
C840  0.22UF  [C0402]
C841  0.22UF  [C0402]
C842  0.22UF  [C0402]
C843  0.22UF  [C0402]
C844  0.22UF  [C0402]
C845  0.22UF  [C0402]
C846  0.22UF  [C0402]
C847  0.22UF  [C0402]
C848  0.22UF  [C0402]
C849  0.22UF  [C0402]
C850  0.22UF  [C0402]
C851  0.22UF  [C0402]
C852  0.22UF  [C0402]
C853  0.22UF  [C0402]
C854  0.22UF  [C0402]
C855  0.22UF  [C0402]
C856  0.22UF  [C0402]
C857  0.22UF  [C0402]
C858  0.22UF  [C0402]
C859  0.22UF  [C0402]
C860  0.22UF  [C0402]
C861  0.22UF  [C0402]
C862  0.22UF  [C0402]
C863  0.22UF  [C0402]
C864  0.22UF  [C0402]
C865  0.22UF  [C0402]
C866  0.1UF  [C0402]
CE15  270UF  [EC83_248_390S]
CE16  330UF  [EC75_248_229S]
J10  PCIEX16  [G_PCI-E_X16_T2A]
R569  10K  [R0603]
R570  10K  [R0603]
R571  10K  [R0603]
R572  0  [R0603]
R573  0  [R0603]
R574  0  [R0402]
R575  0  [R0603]
R576  4.7K  [R0603]
sheet P39  MINI SAS HD for NIC 1&2
C1269  0.22UF  [C0402]
C1270  0.22UF  [C0402]
C1271  0.22UF  [C0402]
C1274  0.22UF  [C0402]
C1276  0.22UF  [C0402]
C1277  0.22UF  [C0402]
C1278  0.22UF  [C0402]
C1279  0.22UF  [C0402]
C1280  0.22UF  [C0402]
C1281  0.22UF  [C0402]
C1282  0.22UF  [C0402]
C1284  0.22UF  [C0402]
C1285  0.22UF  [C0402]
C1286  0.22UF  [C0402]
C1287  0.22UF  [C0402]
C1288  0.22UF  [C0402]
C1289  0.22UF  [C0402]
C1290  0.22UF  [C0402]
C1291  0.22UF  [C0402]
C1292  0.22UF  [C0402]
C1294  0.22UF  [C0402]
C1295  0.22UF  [C0402]
C1298  0.22UF  [C0402]
C1300  0.22UF  [C0402]
C1301  0.22UF  [C0402]
C1302  0.22UF  [C0402]
C1303  0.22UF  [C0402]
C1304  0.22UF  [C0402]
C1305  0.22UF  [C0402]
C1306  0.22UF  [C0402]
C1308  0.22UF  [C0402]
C1309  0.22UF  [C0402]
C1345  0.1UF  [C0402]
C1346  0.1UF  [C0402]
J41  CONN72  [HSD_F72D9H3D_P0-75_LUV]  (sections A,B)
J42  CONN72  [HSD_F72D9H3D_P0-75_LUV]  (sections A,B)
R1073  10K  [R0603]
R1077  0  [R0603]
R1078  0  [R0603]
R1079  0  [R0603]
R1080  0  [R0603]
R1081  10K  [R0603]
R1082  10K  [R0603]
R1083  10K  [R0603]
R1154  0  [R0603]
R1155  0  [R0603]
R1158  0  [R0603]
R1159  0  [R0603]
R1164  4.7K  [R0402]
R1165  4.7K  [R0402]
sheet P40  MINI SAS HD for NIC 3&4
C1310  0.22UF  [C0402]
C1311  0.22UF  [C0402]
C1312  0.22UF  [C0402]
C1313  0.22UF  [C0402]
C1314  0.22UF  [C0402]
C1315  0.22UF  [C0402]
C1316  0.22UF  [C0402]
C1317  0.22UF  [C0402]
C1318  0.22UF  [C0402]
C1319  0.22UF  [C0402]
C1320  0.22UF  [C0402]
C1321  0.22UF  [C0402]
C1322  0.22UF  [C0402]
C1323  0.22UF  [C0402]
C1324  0.22UF  [C0402]
C1325  0.22UF  [C0402]
C1326  0.22UF  [C0402]
C1327  0.22UF  [C0402]
C1328  0.22UF  [C0402]
C1329  0.22UF  [C0402]
C1330  0.22UF  [C0402]
C1331  0.22UF  [C0402]
C1332  0.22UF  [C0402]
C1333  0.22UF  [C0402]
C1334  0.22UF  [C0402]
C1335  0.22UF  [C0402]
C1336  0.22UF  [C0402]
C1337  0.22UF  [C0402]
C1338  0.22UF  [C0402]
C1339  0.22UF  [C0402]
C1340  0.22UF  [C0402]
C1341  0.22UF  [C0402]
C1347  0.1UF  [C0402]
C1348  0.1UF  [C0402]
J43  CONN72  [HSD_F72D9H3D_P0-75_LUV]  (sections A,B)
J45  CONN72  [HSD_F72D9H3D_P0-75_LUV]  (sections A,B)
R1084  0  [R0603]
R1085  0  [R0603]
R1086  0  [R0603]
R1087  0  [R0603]
R1088  10K  [R0603]
R1089  10K  [R0603]
R1090  10K  [R0603]
R1091  10K  [R0603]
R1156  0  [R0603]
R1157  0  [R0603]
R1160  0  [R0603]
R1161  0  [R0603]
R1162  4.7K  [R0402]
R1163  4.7K  [R0402]
sheet P41  Main Board Power Connector
C867  10UF  [C0805_H61]
C868  10UF  [C0805_H61]
C869  1000PF  [C0402]
C870  10UF  [C0805_H61]
C871  0.1UF  [C0402]
C872  10UF  [C0603]
C873  10UF  [C0805_H61]
C874  1000PF  [C0402]
C1374  0.1UF  [C0402]
C1375  22UF  [C0805_H61]
C1377  22UF  [C0805_H61]
C1378  22UF  [C0805_H61]
C1379  0.1UF  [C0402]
C1380  0.1UF  [C0402]
C1381  0.1UF  [C0402]
C1382  0.1UF  [C0402]
C1383  1UF  [C0603]
C1384  0.1UF  [C0402]
C1385  0.1UF  [C0402]
C1386  0.1UF  [C0402]
C1387  0.1UF  [C0402]
C1388  22UF  [C0805_H61]
J11  CONN24  [CON_PWR2X12HXB]
J12  PWR_CON_2X4  [CON_PWR2X4XA]
J13  PWR_CON_2X4  [CON_PWR2X4XA]
J46  CONN6  [CON_PWR2X3]
R578  0  [R0402]
R1172  2.74K  [R0603]
sheet P42  PCIe Power Connector
C875  10UF  [C0805_H61]
C876  1000PF  [C0402]
C877  10UF  [C0805_H61]
C878  1000PF  [C0402]
C879  10UF  [C0805_H61]
C880  1000PF  [C0402]
C881  10UF  [C0805_H61]
C882  1000PF  [C0402]
C883  10UF  [C0805_H61]
C884  1000PF  [C0402]
C885  10UF  [C0805_H61]
C886  1000PF  [C0402]
C887  10UF  [C0805_H61]
C888  1000PF  [C0402]
C889  10UF  [C0805_H61]
C890  1000PF  [C0402]
CE17  470UF  [EC181_394_496S]
CE18  470UF  [EC181_394_496S]
CE19  470UF  [EC181_394_496S]
CE20  470UF  [EC181_394_496S]
CE21  470UF  [EC181_394_496S]
CE22  470UF  [EC181_394_496S]
CE23  470UF  [EC181_394_496S]
CE24  470UF  [EC181_394_496S]
J14  CONN8  [CON_PWR2X4HRXC]
J15  CONN8  [CON_PWR2X4HRXC]
J16  CONN8  [CON_PWR2X4HRXC]
J17  CONN8  [CON_PWR2X4HRXC]
J18  CONN8  [CON_PWR2X4HRXC]
J19  CONN8  [CON_PWR2X4HRXC]
J20  CONN8  [CON_PWR2X4HRXC]
J21  CONN8  [CON_PWR2X4HRXC]
sheet P44  FRU & Temperature Sensor
C1003  0.1UF  [C0402]
C1004  0.1UF  [C0402]
C1219  0.1UF  [C0402]
R767  10K  [R0603]
R768  10K  [R0603]
R769  10K  [R0603]
R770  10K  [R0603]
R771  10K  [R0603]
R772  4.7K  [R0402]
R773  4.7K  [R0402]
R774  4.7K  [R0402]
R775  0  [R0603]
R776  0  [R0603]
R777  10K  [R0603]
R778  10K  [R0603]
R779  10K  [R0603]
R780  4.7K  [R0603]
R781  100  [R0402]
R782  100  [R0402]
R783  100  [R0402]
R845  0  [R0603]
R846  0  [R0603]
R847  10K  [R0603]
R848  10K  [R0603]
R884  4.7K  [R0402]
R885  4.7K  [R0402]
R886  4.7K  [R0402]
R887  100  [R0402]
R888  100  [R0402]
R889  100  [R0402]
R890  0  [R0603]
R891  0  [R0603]
R892  10K  [R0603]
R893  10K  [R0603]
U17  TMP75AIDR  [SOIC8]
U18  M24C64  [SOIC8]
U102  TMP75AIDR  [SOIC8]
sheet P45  SMBus & PMBus Connector
C897  22UF  [C0805_H61]
C898  0.1UF  [C0402]
C899  0.1UF  [C0402]
C900  47PF  [C0402]
C901  22UF  [C0805_H61]
J27  CONN7  [HEADER1X7BH]
J28  HEADER 1X5  [HEADER1X5BHXA]
J29  HEADER 1X4  [HEADER1X4BHXA]
R579  4.7K  [R0402]
R580  4.7K  [R0402]
R585  0  [R0402]
R586  3.3K  [R0402]
R587  3.3K  [R0402]
R588  10K  [R0402]
R589  150  [R0402]
R590  10K  [R0603]
R591  10K  [R0603]
R592  10K  [R0603]
R597  4.7K  [R0402]
R598  4.7K  [R0402]
U77  IC  [SSOP8]
sheet P46  SMBus Multiplexer
C902  0.1UF  [C0402]
C903  0.1UF  [C0402]
C1350  0.1UF  [C0402]
R599  10K  [R0603]
R600  10K  [R0603]
R601  10K  [R0603]
R602  10K  [R0603]
R603  10K  [R0603]
R604  10K  [R0603]
R605  10K  [R0603]
R606  10K  [R0603]
R607  10K  [R0603]
R608  10K  [R0603]
R609  10K  [R0603]
R610  10K  [R0603]
R611  10K  [R0603]
R612  10K  [R0603]
R613  10K  [R0603]
R614  10K  [R0603]
R615  10K  [R0603]
R616  10K  [R0603]
R617  0  [R0603]
R618  0  [R0603]
R619  0  [R0603]
R620  10K  [R0603]
R621  10K  [R0603]
R622  10K  [R0603]
R623  10K  [R0603]
R624  10K  [R0603]
R625  10K  [R0603]
R626  10K  [R0603]
R627  10K  [R0603]
R628  10K  [R0603]
R629  10K  [R0603]
R630  10K  [R0603]
R631  10K  [R0603]
R632  10K  [R0603]
R633  10K  [R0603]
R634  10K  [R0603]
R635  10K  [R0603]
R636  10K  [R0603]
R637  10K  [R0603]
R638  0  [R0603]
R639  0  [R0603]
R640  0  [R0603]
R641  10K  [R0603]
R642  10K  [R0603]
R643  10K  [R0603]
R644  10K  [R0603]
R645  10K  [R0603]
R646  10K  [R0603]
R851  220  [R0402]
R852  220  [R0402]
R853  220  [R0402]
R854  220  [R0402]
R1071  10K  [R0603]
R1072  10K  [R0603]
R1119  0  [R0603]
R1120  0  [R0603]
R1121  0  [R0603]
R1122  10K  [R0603]
R1123  10K  [R0603]
R1124  10K  [R0603]
R1125  10K  [R0603]
R1126  10K  [R0603]
R1127  10K  [R0603]
R1128  10K  [R0603]
R1129  10K  [R0603]
R1130  10K  [R0603]
R1131  10K  [R0603]
R1136  220  [R0402]
R1137  220  [R0402]
R1138  220  [R0402]
R1139  220  [R0402]
R1141  10K  [R0603]
R1142  10K  [R0603]
R1144  10K  [R0603]
R1145  10K  [R0603]
R1146  220  [R0402]
R1147  220  [R0402]
R1148  220  [R0402]
R1149  220  [R0402]
R1150  10K  [R0603]
R1151  10K  [R0603]
U8  IC  [TSSOP24]
U9  IC  [TSSOP24]
U105  IC  [TSSOP24]
sheet P47  PLX I2C Debug Header
C904  0.1UF  [C0402]
C905  0.1UF  [C0402]
C906  0.1UF  [C0402]
C907  0.1UF  [C0402]
JP2  HEADER 1X3  [G_HEADER1X3]
JP3  HEADER 1X3  [G_HEADER1X3]
R647  10K  [R0603]
R648  10K  [R0603]
R649  200K  [R0402]
R650  10K  [R0603]
R651  10K  [R0603]
R652  0  [R0603]
R653  0  [R0603]
R654  10K  [R0603]
R655  10K  [R0603]
R656  200K  [R0402]
R657  10K  [R0603]
R658  10K  [R0603]
R659  0  [R0603]
R660  0  [R0603]
U10  IC  [SSOP8]
U11  IC  [SSOP8]
sheet P48  P12V_STBY Hot Swap
C1215  0.1UF  [C0402]
C1216  0.1UF  [C0402]
C1217  1UF  [C0402]
C1218  0.1UF  [C0402]
D19  SS14  [D2010]
D20  SMAJ13A-13-F  [D2010XF]
PC212  0.047UF  [C0402]
PC213  0.22UF  [C0402]
PC1440  100UF  [EC56_197_229S]
PR248  200K  [R0402]
PR249  11.8K  [R0402]
PR250  3.4K  [R0402]
PR251  0  [R0402]
PR252  150K  [R0402]
PR253  365K  [R0402]
PR254  240K  [R0402]
PR255  510K  [R0402]
U28  IC  [QFN22_TH_3X5]

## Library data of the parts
C823-C827 C831 C832 C834-C866 C869 C871 C874 C876 C878 C880 C882 C884 C886 C888 C890 C898-C900 C904-C907 C1215-C1218 C1269-C1271 C1274 C1276-C1282 C1284-C1292 C1294 C1295 C1298 C1300-C1306 C1308-C1341 C1345-C1348 PC212 PC213 = CAP_NP: Part_Type: *LF_C0402
C828 = CAP_NP: Part_Type: *LF_C1206
C829 C833 C867 C868 C870 C873 C875 C877 C879 C881 C883 C885 C887 C889 C901 = CAP_NP: Part_Type: *LF_C0805
C830 C872 = CAP_NP: Part_Type: *LF_C0603
CE15-CE24 PC1440 = CAPACITOR_POL: Part_Type: *LF_C_ELEC_SMD
J10 = PCI_EXPRESS_X16_CONN: DIP_SMD: DIP; Part_Type: *LF_Connector
R569-R571 R599 R600 R623-R627 R642-R644 R647 R648 R654 R655 R1073 R1081-R1083 R1088-R1091 R1122 R1123 R1144 R1145 R1150 = R: Not_insert: NI; Part_Type: *LF_Resistor; WATTAGE: 1/10W
R572 R573 R575 R576 R590-R592 R601-R622 R628-R641 R645 R646 R650-R653 R657-R660 R1071 R1072 R1077-R1080 R1084-R1087 R1119-R1121 R1124-R1131 R1141 R1142 R1151 R1154-R1161 R1172 = R: Part_Type: *LF_Resistor; WATTAGE: 1/10W
PR250 PR252 PR255 R574 R578 R589 R649 R656 R1162-R1165 = R: Part_Type: *LF_Resistor; WATTAGE: 1/16W
J41-J43 J45 = CONN72_10112633101LF: DIP_SMD: DIP; Part_Type: *LF_Connector
C1374 C1379-C1382 C1384-C1387 = CAP_NP: Not_insert: NI; Part_Type: *LF_C0402
C897 C1375 C1377 C1378 C1388 = CAP_NP: Not_insert: NI; Part_Type: *LF_C0805
C1383 = CAP_NP: Not_insert: NI; Part_Type: *LF_C0603
J11 = CONN24_ABAPOW013T55: DIP_SMD: DIP; Part_Type: *LF_Connector
J12 J13 = E-Bay+12V_Power_Conn: DIP_SMD: DIP; Part_Type: *LF_Connector
J46 = CONN6_460150602: DIP_SMD: DIP; Not_insert: NI; Part_Type: *LF_Connector
J14-J21 = CONN8_ABAPOW050P07: DIP_SMD: DIP; Part_Type: *LF_Connector
C1003 C1004 = CAP_NP: Manuf_name: MURATA ERIE N.A. INC TAIWAN BRANCH Okayama Murata Mfg.Co..Ltd. Wakura Murata Mfg; Part_Type: *LF_C0402
C1219 = CAP_NP: Manuf_name: MURATA ERIE N.A. INC TAIWAN BRANCH Okayama Murata Mfg.Co..Ltd. Wakura Murata Mfg; Not_insert: NI; Part_Type: *LF_C0402
R767 R768 R777-R779 R847 R848 R892 R893 = R: Manuf_name: MATSUSHITA ELECTRONICS CORPORATION (PANASONIC)Wuxi Matsushita Battery Co.. Ltd; Not_insert: NI; Part_Type: *LF_Resistor; WATTAGE: 1/10W
R769-R771 R780 = R: Manuf_name: MATSUSHITA ELECTRONICS CORPORATION (PANASONIC)Wuxi Matsushita Battery Co.. Ltd; Part_Type: *LF_Resistor; WATTAGE: 1/10W
R772 R782 R783 = R_0: Manuf_name: CYNTEC CO.. LTD.; Part_Type: *LF_Resistor; WATTAGE: 1/16W
R773 R774 R781 R884-R889 = R_0: Manuf_name: CYNTEC CO.. LTD.; Not_insert: NI; Part_Type: *LF_Resistor; WATTAGE: 1/16W
R775 R776 R845 R846 = R: Manuf_name: DALE ELECTRONICS.INC.; Part_Type: *LF_Resistor; WATTAGE: 1/10W
R890 R891 = R: Manuf_name: DALE ELECTRONICS.INC.; Not_insert: NI; Part_Type: *LF_Resistor; WATTAGE: 1/10W
U17 = TMP75AIDR: Manuf_name: TEXAS INSTRUMENTS SUPPLY CO.; Part_Type: Chipset
U18 = AT24C32: Manuf_name: SGS-THOMSON(STMicroelectronics); Part_Type: *LF_Chipset
U102 = TMP75AIDR: Manuf_name: TEXAS INSTRUMENTS SUPPLY CO.; Not_insert: NI; Part_Type: Chipset
J27 = CONN7_HF5507EP1: Part_Type: *LF_Connector
J28 = HEADER1X5_3: Part_Type: *LF_Connector
J29 = IPMB_CONN_1: Part_Type: *LF_Connector
R579 R580 R585-R588 R597 R598 = R: Not_insert: NI; Part_Type: *LF_Resistor; WATTAGE: 1/16W
U10 U11 U77 = PCA9306DCTR: Part_Type: *LF_Chipset
C902 C903 C1350 = CAP_NP: From_pj: T2A-TONY; Part_Type: *LF_C0402; fp_ECN: 0402 SERIES_LL34.xls
R851-R854 R1136-R1139 R1146-R1149 = R: Part_Type: *LF_Resistor; WATTAGE: 1/16W; fp_ECN: 0402 SERIES_LL34.xls
U8 U9 U105 = PCA9548APW: From_pj: LB6-EDDY; Part_Type: *LF_Chipset
JP2 JP3 = HEADER_1X3: Not_insert: NI; Part_Type: *LF_Connector
D19 = SCHOTTKY_0: Not_insert: NI; Part_Type: *LF_Semiconductor
D20 = PTZ15B: Part_Type: *LF_Semiconductor
PR248 PR249 PR253 = R_0: Part_Type: *LF_Resistor; WATTAGE: 1/16W
PR251 = R_0: Not_insert: NI; Part_Type: *LF_Resistor; WATTAGE: 1/16W
PR254 = R: Part_Type: Resistor; WATTAGE: 1/16W
U28 = MP5021BGQVZ: Part_Type: *LF_Chipset

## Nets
12VN: J11.14(12VN)
GND: C823.2 C824.2 C825.2 C826.2 C827.2 C828.2 C829.2 C830.2 C831.2 C832.2 C833.2 C866.2 C867.2 C868.2 C869.2 C870.2 C871.2 C872.2 C873.2 C874.2 C875.2 C876.2 C877.2 C878.2 C879.2 C880.2 C881.2 C882.2 C883.2 C884.2 C885.2 C886.2 C887.2 C888.2 C889.2 C890.2 C897.2 C898.2 C899.2 C900.2 C901.2 C902.2 C903.2 C904.2 C905.2 C906.2 C907.2 C1003.2 C1004.2 C1215.2 C1216.2 C1217.2 C1218.2 C1219.2 C1345.2 C1346.2 C1347.2 C1348.2 C1350.2 C1374.2 C1375.2 C1377.2 C1378.2 C1379.2 C1380.2 C1381.2 C1382.2 C1383.2 C1384.2 C1385.2 C1386.2 C1387.2 C1388.2 CE15.2 CE16.2 CE17.2 CE18.2 CE19.2 CE20.2 CE21.2 CE22.2 CE23.2 CE24.2 D19.1(A) D20.A J10.A1(PRSNT1_N) J10.A4(GND35) J10.A12(GND36) J10.A15(GND37) J10.A18(GND38) J10.A20(GND39) J10.A23(GND40) J10.A24(GND41) J10.A27(GND42) J10.A28(GND43) J10.A31(GND44) J10.A34(GND45) J10.A37(GND46) J10.A38(GND47) J10.A41(GND48) J10.A42(GND49) J10.A45(GND50) J10.A46(GND51) J10.A49(GND52) J10.A51(GND53) J10.A54(GND54) J10.A55(GND55) J10.A58(GND56) J10.A59(GND57) J10.A62(GND58) J10.A63(GND59) J10.A66(GND60) J10.A67(RSVD8) J10.A70(GND61) J10.A71(GND62) J10.A74(GND63) J10.A75(GND64) J10.A78(GND65) J10.A79(GND66) J10.A82(GND67) J10.B4(GND1) J10.B7(GND2) J10.B13(GND3) J10.B16(GND4) J10.B18(GND5) J10.B21(GND6) J10.B22(GND7) J10.B25(GND8) J10.B26(GND9) J10.B29(GND10) J10.B32(GND11) J10.B35(GND12) J10.B36(GND13) J10.B39(GND14) J10.B40(GND15) J10.B43(GND16) J10.B44(GND17) J10.B47(GND18) J10.B49(GND19) J10.B52(GND20) J10.B53(GND21) J10.B56(GND22) J10.B57(GND23) J10.B60(GND24) J10.B61(GND25) J10.B64(GND26) J10.B65(GND27) J10.B68(GND28) J10.B69(GND29) J10.B72(GND30) J10.B73(GND31) J10.B76(GND32) J10.B77(GND33) J10.B80(GND34) J11.3(COM_0) J11.5(COM_1) J11.7(COM_2) J11.15(COM_3) J11.17(COM_4) J11.18(COM_5) J11.19(COM_6) J11.24(COM_7) J12.1(GND1) J12.2(GND2) J12.3(GND3) J12.4(GND4) J13.1(GND1) J13.2(GND2) J13.3(GND3) J13.4(GND4) J14.5 J14.6 J14.7 J14.8 J15.5 J15.6 J15.7 J15.8 J16.5 J16.6 J16.7 J16.8 J17.5 J17.6 J17.7 J17.8 J18.5 J18.6 J18.7 J18.8 J19.5 J19.6 J19.7 J19.8 J20.5 J20.6 J20.7 J20.8 J21.5 J21.6 J21.7 J21.8 J27.2 J28.4 J29.2 J41.A3_1(GND) J41.A3_2(GND) J41.A6_1(GND) J41.A6_2(GND) J41.A9_1(GND) J41.A9_2(GND) J41.B3_1(GND) J41.B3_2(GND) J41.B6_1(GND) J41.B6_2(GND) J41.B9_1(GND) J41.B9_2(GND) J41.C3_1(GND) J41.C3_2(GND) J41.C6_1(GND) J41.C6_2(GND) J41.C9_1(GND) J41.C9_2(GND) J41.D3_1(GND) J41.D3_2(GND) J41.D6_1(GND) J41.D6_2(GND) J41.D9_1(GND) J41.D9_2(GND) J41.MG1 J41.MG2 J41.MG3 J42.A3_1(GND) J42.A3_2(GND) J42.A6_1(GND) J42.A6_2(GND) J42.A9_1(GND) J42.A9_2(GND) J42.B3_1(GND) J42.B3_2(GND) J42.B6_1(GND) J42.B6_2(GND) J42.B9_1(GND) J42.B9_2(GND) J42.C3_1(GND) J42.C3_2(GND) J42.C6_1(GND) J42.C6_2(GND) J42.C9_1(GND) J42.C9_2(GND) J42.D3_1(GND) J42.D3_2(GND) J42.D6_1(GND) J42.D6_2(GND) J42.D9_1(GND) J42.D9_2(GND) J42.MG1 J42.MG2 J42.MG3 J43.A3_1(GND) J43.A3_2(GND) J43.A6_1(GND) J43.A6_2(GND) J43.A9_1(GND) J43.A9_2(GND) J43.B3_1(GND) J43.B3_2(GND) J43.B6_1(GND) J43.B6_2(GND) J43.B9_1(GND) J43.B9_2(GND) J43.C3_1(GND) J43.C3_2(GND) J43.C6_1(GND) J43.C6_2(GND) J43.C9_1(GND) J43.C9_2(GND) J43.D3_1(GND) J43.D3_2(GND) J43.D6_1(GND) J43.D6_2(GND) J43.D9_1(GND) J43.D9_2(GND) J43.MG1 J43.MG2 J43.MG3 J45.A3_1(GND) J45.A3_2(GND) J45.A6_1(GND) J45.A6_2(GND) J45.A9_1(GND) J45.A9_2(GND) J45.B3_1(GND) J45.B3_2(GND) J45.B6_1(GND) J45.B6_2(GND) J45.B9_1(GND) J45.B9_2(GND) J45.C3_1(GND) J45.C3_2(GND) J45.C6_1(GND) J45.C6_2(GND) J45.C9_1(GND) J45.C9_2(GND) J45.D3_1(GND) J45.D3_2(GND) J45.D6_1(GND) J45.D6_2(GND) J45.D9_1(GND) J45.D9_2(GND) J45.MG1 J45.MG2 J45.MG3 J46.1 J46.2 J46.3 JP2.2 JP3.2 PC212.1 PC213.1 PC1440.2 PR249.1 PR250.2 PR251.1 PR252.2 PR254.2 R623.2 R624.2 R625.2 R644.2 R645.2 R646.2 R777.2 R778.2 R779.2 R780.1 R781.1 R782.1 R783.1 R851.2 R852.2 R853.2 R854.2 R887.1 R888.1 R889.1 R1136.2 R1137.2 R1138.2 R1139.2 R1141.2 R1142.2 R1146.2 R1147.2 R1148.2 R1149.2 R1151.2 U8.12(VSS) U9.12(VSS) U10.1(GND) U11.1(GND) U17.4(GND) U18.4(GND) U28.7(GND) U77.1(GND) U102.4(GND) U105.12(VSS) ; also on sheet 3 4 5 6 7 8 9 10 11 12 13 14 15 16 17 18 19 20 21 22 23 24 25 26 27 28 29 30 31 32 33 34 35 36 37 48 49 50 51 52 53 54 55 56 57 58 59 60 61 62 63 64 65 66 67
P1V8D_PLX1: C905.1 R650.1 R651.1 U10.2(VREF1) ; also on sheet 9 10 11 12 14 51 60
P1V8D_PLX2: C907.1 R657.1 R658.1 U11.2(VREF1) ; also on sheet 21 22 23 24 26 51 61
P3V3: C831.1 C832.1 C833.1 C872.1 C1377.1 C1378.1 C1379.1 C1380.1 C1381.1 CE16.1 J10.A9(3.3V_2) J10.A10(3.3V_3) J10.B8(3.3V_1) J11.1(3V3P_0) J11.2(3V3P_1) J11.12(3V3P_2) J11.13(3V3P_3) J46.6 R585.1 ; also on sheet 10 22 27 28 31 32 33 34 35 36 37 51 53 59 60 61 62 63 64 65 66
P3V3_PMBUS: J28.5 R585.2
P3V3_STBY: C829.1 C830.1 C898.1 C899.1 C901.1 C902.1 C903.1 C904.1 C906.1 C1003.1 C1004.1 C1219.1 C1345.1 C1346.1 C1347.1 C1348.1 C1350.1 J10.B10(3.3VAUX) J29.4 R569.1 R570.1 R571.1 R576.2 R586.1 R587.1 R588.1 R590.1 R591.1 R592.1 R597.1 R598.1 R601.1 R602.1 R603.1 R604.1 R605.1 R606.1 R607.1 R608.1 R609.1 R610.1 R611.1 R612.1 R613.1 R614.1 R615.1 R616.1 R620.1 R621.1 R622.1 R628.1 R629.1 R630.1 R631.1 R632.1 R633.1 R634.1 R635.1 R636.1 R637.1 R641.1 R642.1 R643.1 R647.1 R648.1 R649.1 R654.1 R655.1 R656.1 R767.1 R768.1 R769.1 R770.1 R771.1 R772.2 R773.2 R774.2 R847.1 R848.1 R884.2 R885.2 R886.2 R892.1 R893.1 R1071.1 R1072.1 R1073.2 R1081.2 R1082.2 R1083.2 R1088.2 R1089.2 R1090.2 R1091.2 R1124.1 R1125.1 R1126.1 R1127.1 R1128.1 R1129.1 R1130.1 R1131.1 R1144.1 R1145.1 R1150.1 R1162.1 R1163.1 R1164.1 R1165.1 U8.24(VDD) U9.24(VDD) U17.8(VCC) U18.8(VCC) U77.2(VREF1) U77.7(VREF2) U102.8(VCC) U105.24(VDD) ; also on sheet 27 28 29 30 31 32 33 34 35 36 37 48 49 50 51 54 55 58 67
P5V: C870.1 J11.4(5VP_0) J11.6(5VP_1) J11.21(5VP_2) J11.22(5VP_3) J11.23(5VP_4) ; also on sheet 51 57 59 60 61 62 63 66
P5V_STBY: C897.1 C1382.1 C1383.1 J11.9(5VSB) J46.5 R579.1 R580.1 R599.1 R600.1 R626.1 R627.1 R1122.1 R1123.1 R1172.1 ; also on sheet 51 56
P12V: C867.1 C868.1 C869.1 C873.1 C874.1 C879.1 C880.1 C885.1 C886.1 C1374.1 C1375.1 C1384.1 C1385.1 C1386.1 C1387.1 C1388.1 CE19.1 CE22.1 J11.10(12V4P_0) J11.11(12V4P_1) J12.5(+12V3_1) J12.6(+12V3_2) J12.7(+12V3_3) J12.8(+12V3_4) J13.5(+12V3_1) J13.6(+12V3_2) J13.7(+12V3_3) J13.8(+12V3_4) J17.1 J17.2 J17.3 J17.4 J18.1 J18.2 J18.3 J18.4 J46.4 ; also on sheet 34 35 50 57 59 66
P12V_1: C883.1 C884.1 C887.1 C888.1 C889.1 C890.1 CE21.1 CE23.1 CE24.1 J19.1 J19.2 J19.3 J19.4 J20.1 J20.2 J20.3 J20.4 J21.1 J21.2 J21.3 J21.4 ; also on sheet 31 32 33 48 52 60 62 64
P12V_2: C823.1 C824.1 C825.1 C826.1 C827.1 C828.1 C875.1 C876.1 C877.1 C878.1 C881.1 C882.1 CE15.1 CE17.1 CE18.1 CE20.1 J10.A2(12V_4) J10.A3(12V_5) J10.B1(12V_1) J10.B2(12V_2) J10.B3(12V_3) J14.1 J14.2 J14.3 J14.4 J15.1 J15.2 J15.3 J15.4 J16.1 J16.2 J16.3 J16.4 ; also on sheet 36 37 49 52 61 63 65
P12V_PSU: C1216.1 D20.C PR253.1 U28.21_22(VIN1) U28.23(VIN_EP1) U28.24(VIN_EP2) U28.25(VIN_EP3) U28.26(VIN_EP4) ; also on sheet 48 49 50
P12V_STBY: C1215.1 D19.2(C) PC1440.1 PR248.2 PR255.1 U28.12(PD) U28.13(OUT8) U28.14(OUT7) U28.15(OUT6) U28.16(OUT5) U28.17(OUT4) U28.18(OUT3) U28.19(OUT2) U28.20(OUT1) ; also on sheet 51 56 58
P12V_STBY_HSC_AUTO: PR251.2 U28.2(AUTO)
P12V_STBY_HSC_EN: C1218.1 PR252.1 PR253.2 U28.1(EN)
P12V_STBY_HSC_ENTM: C1217.1 U28.3(ENTM)
P12V_STBY_HSC_FB: PR248.1 PR249.2 U28.11(FB)
P12V_STBY_HSC_ISET: PR250.1 U28.5(ISET)
P12V_STBY_HSC_SS: PC212.2 U28.6(SS)
P12V_STBY_HSC_TIMER: PC213.2 U28.4(TIMER)
P12V_STBY_PWRGD: PR254.1 PR255.2 U28.10(PG) ; also on sheet 56
ADDR_FRU_A0: R771.2 R779.1 U18.1(A0)
ADDR_FRU_A1: R770.2 R778.1 U18.2(A1)
ADDR_FRU_A2: R769.2 R777.1 U18.3(A2)
ADDR_PCA9548_A_A0: R622.2 R625.1 U8.1(A0)
ADDR_PCA9548_A_A1: R621.2 R624.1 U8.2(A1)
ADDR_PCA9548_A_A2: R620.2 R623.1 U8.21(A2)
ADDR_PCA9548_B_A0: R643.2 R646.1 U9.1(A0)
ADDR_PCA9548_B_A1: R642.2 R645.1 U9.2(A1)
ADDR_PCA9548_B_A2: R641.2 R644.1 U9.21(A2)
ADDR_PCA9548_C_A0: R1141.1 R1144.2 U105.1(A0)
ADDR_PCA9548_C_A1: R1142.1 R1145.2 U105.2(A1)
ADDR_PCA9548_C_A2: R1150.2 R1151.1 U105.21(A2)
ADDR_TMP75_2_A0: R886.1 R889.2 U102.7(A0)
ADDR_TMP75_2_A1: R885.1 R887.2 U102.6(A1)
ADDR_TMP75_2_A2: R884.1 R888.2 U102.5(A2)
ADDR_TMP75_A0: R774.1 R783.2 U17.7(A0)
ADDR_TMP75_A1: R773.1 R782.2 U17.6(A1)
ADDR_TMP75_A2: R772.1 R781.2 U17.5(A2)
CLK_100M_NIC1_DN: J41.A2_2(IntL_2) ; also on sheet 27
CLK_100M_NIC1_DP: J41.A1_2(Reserved_2) ; also on sheet 27
CLK_100M_NIC2_DN: J42.A2_2(IntL_2) ; also on sheet 27
CLK_100M_NIC2_DP: J42.A1_2(Reserved_2) ; also on sheet 27
CLK_100M_NIC3_DN: J43.A2_2(IntL_2) ; also on sheet 28
CLK_100M_NIC3_DP: J43.A1_2(Reserved_2) ; also on sheet 28
CLK_100M_NIC4_DN: J45.A2_2(IntL_2) ; also on sheet 28
CLK_100M_NIC4_DP: J45.A1_2(Reserved_2) ; also on sheet 28
CLK_100M_PE7_N: J10.A14(REFCLK-) ; also on sheet 28
CLK_100M_PE7_P: J10.A13(REFCLK+) ; also on sheet 28
FM_PS_ON_N: C871.1 J11.16(PS_ON) R578.1 R1172.2
FM_PWR_EN_N: R578.2 ; also on sheet 67
GPU_THROTTLE_SLOT7_N: R574.1 ; also on sheet 67
GPU_THROTTLE_SLOT7_R_N: J10.B12(RSVD1) R571.2 R574.2
NIC1_PRESET_N: R1159.1 ; also on sheet 27
NIC1_PRESET_R_N: J41.B2_2(ModPrsL_2) R1159.2 R1164.2
NIC2_PRESET_N: R1158.1 ; also on sheet 27
NIC2_PRESET_R_N: J42.B2_2(ModPrsL_2) R1158.2 R1165.2
NIC3_PRESET_N: R1160.1 ; also on sheet 28
NIC3_PRESET_R_N: J43.B2_2(ModPrsL_2) R1160.2 R1162.2
NIC4_PRESET_N: R1161.1 ; also on sheet 28
NIC4_PRESET_R_N: J45.B2_2(ModPrsL_2) R1161.2 R1163.2
PCIE_WAKE_NIC1_N: J41.C1_1(SCL_1) ; also on sheet 29
PCIE_WAKE_NIC3_N: J43.C1_1(SCL_1) ; also on sheet 29
PD_FRU_WP: R780.2 U18.7(WP)
PD_PCA9548_B_SC6: R851.1 U9.18(SC6)
PD_PCA9548_B_SC7: R854.1 U9.20(SC7)
PD_PCA9548_B_SD6: R852.1 U9.17(SD6)
PD_PCA9548_B_SD7: R853.1 U9.19(SD7)
PD_PCA9548_C_SC4: R1147.1 U105.14(SC4)
PD_PCA9548_C_SC5: R1148.1 U105.16(SC5)
PD_PCA9548_C_SC6: R1137.1 U105.18(SC6)
PD_PCA9548_C_SC7: R1139.1 U105.20(SC7)
PD_PCA9548_C_SD4: R1146.1 U105.13(SD4)
PD_PCA9548_C_SD5: R1149.1 U105.15(SD5)
PD_PCA9548_C_SD6: R1136.1 U105.17(SD6)
PD_PCA9548_C_SD7: R1138.1 U105.19(SD7)
PE_SLOT7_PRSNT_N: C866.1 J10.B17(PRSNT2_N-1) J10.B31(PRSNT2_N-2) J10.B48(PRSNT2_N-3) J10.B81(PRSNT2_N-4) R576.1 ; also on sheet 28
PEX_NIC1_RXN0: J41.D5_1(TX0N_1) ; also on sheet 4
PEX_NIC1_RXN1: J41.C5_1(TX1N_1) ; also on sheet 4
PEX_NIC1_RXN2: J41.D8_1(TX2N_1) ; also on sheet 4
PEX_NIC1_RXN3: J41.C8_1(TX3N_1) ; also on sheet 4
PEX_NIC1_RXN4: J41.D5_2(TX0N_2) ; also on sheet 4
PEX_NIC1_RXN5: J41.C5_2(TX1N_2) ; also on sheet 4
PEX_NIC1_RXN6: J41.D8_2(TX2N_2) ; also on sheet 4
PEX_NIC1_RXN7: J41.C8_2(TX3N_2) ; also on sheet 4
PEX_NIC1_RXP0: J41.D4_1(TX0P_1) ; also on sheet 4
PEX_NIC1_RXP1: J41.C4_1(TX1P_1) ; also on sheet 4
PEX_NIC1_RXP2: J41.D7_1(TX2P_1) ; also on sheet 4
PEX_NIC1_RXP3: J41.C7_1(TX3P_1) ; also on sheet 4
PEX_NIC1_RXP4: J41.D4_2(TX0P_2) ; also on sheet 4
PEX_NIC1_RXP5: J41.C4_2(TX1P_2) ; also on sheet 4
PEX_NIC1_RXP6: J41.D7_2(TX2P_2) ; also on sheet 4
PEX_NIC1_RXP7: J41.C7_2(TX3P_2) ; also on sheet 4
PEX_NIC1_TXN0: C1308.1 ; also on sheet 4
PEX_NIC1_TXN0_C: C1308.2 J41.B5_1(RX0N_1)
PEX_NIC1_TXN1: C1269.1 ; also on sheet 4
PEX_NIC1_TXN1_C: C1269.2 J41.A5_1(RX1N_1)
PEX_NIC1_TXN2: C1300.1 ; also on sheet 4
PEX_NIC1_TXN2_C: C1300.2 J41.B8_1(RX2N_1)
PEX_NIC1_TXN3: C1278.1 ; also on sheet 4
PEX_NIC1_TXN3_C: C1278.2 J41.A8_1(RX3N_1)
PEX_NIC1_TXN4: C1276.1 ; also on sheet 4
PEX_NIC1_TXN4_C: C1276.2 J41.B5_2(RX0N_2)
PEX_NIC1_TXN5: C1304.1 ; also on sheet 4
PEX_NIC1_TXN5_C: C1304.2 J41.A5_2(RX1N_2)
PEX_NIC1_TXN6: C1289.1 ; also on sheet 4
PEX_NIC1_TXN6_C: C1289.2 J41.B8_2(RX2N_2)
PEX_NIC1_TXN7: C1301.1 ; also on sheet 4
PEX_NIC1_TXN7_C: C1301.2 J41.A8_2(RX3N_2)
PEX_NIC1_TXP0: C1292.1 ; also on sheet 4
PEX_NIC1_TXP0_C: C1292.2 J41.B4_1(RX0P_1)
PEX_NIC1_TXP1: C1281.1 ; also on sheet 4
PEX_NIC1_TXP1_C: C1281.2 J41.A4_1(RX1P_1)
PEX_NIC1_TXP2: C1306.1 ; also on sheet 4
PEX_NIC1_TXP2_C: C1306.2 J41.B7_1(RX2P_1)
PEX_NIC1_TXP3: C1279.1 ; also on sheet 4
PEX_NIC1_TXP3_C: C1279.2 J41.A7_1(RX3P_1)
PEX_NIC1_TXP4: C1298.1 ; also on sheet 4
PEX_NIC1_TXP4_C: C1298.2 J41.B4_2(RX0P_2)
PEX_NIC1_TXP5: C1286.1 ; also on sheet 4
PEX_NIC1_TXP5_C: C1286.2 J41.A4_2(RX1P_2)
PEX_NIC1_TXP6: C1288.1 ; also on sheet 4
PEX_NIC1_TXP6_C: C1288.2 J41.B7_2(RX2P_2)
PEX_NIC1_TXP7: C1274.1 ; also on sheet 4
PEX_NIC1_TXP7_C: C1274.2 J41.A7_2(RX3P_2)
PEX_NIC2_RXN8: J42.D5_1(TX0N_1) ; also on sheet 4
PEX_NIC2_RXN9: J42.C5_1(TX1N_1) ; also on sheet 4
PEX_NIC2_RXN10: J42.D8_1(TX2N_1) ; also on sheet 4
PEX_NIC2_RXN11: J42.C8_1(TX3N_1) ; also on sheet 4
PEX_NIC2_RXN12: J42.D5_2(TX0N_2) ; also on sheet 4
PEX_NIC2_RXN13: J42.C5_2(TX1N_2) ; also on sheet 4
PEX_NIC2_RXN14: J42.D8_2(TX2N_2) ; also on sheet 4
PEX_NIC2_RXN15: J42.C8_2(TX3N_2) ; also on sheet 4
PEX_NIC2_RXP8: J42.D4_1(TX0P_1) ; also on sheet 4
PEX_NIC2_RXP9: J42.C4_1(TX1P_1) ; also on sheet 4
PEX_NIC2_RXP10: J42.D7_1(TX2P_1) ; also on sheet 4
PEX_NIC2_RXP11: J42.C7_1(TX3P_1) ; also on sheet 4
PEX_NIC2_RXP12: J42.D4_2(TX0P_2) ; also on sheet 4
PEX_NIC2_RXP13: J42.C4_2(TX1P_2) ; also on sheet 4
PEX_NIC2_RXP14: J42.D7_2(TX2P_2) ; also on sheet 4
PEX_NIC2_RXP15: J42.C7_2(TX3P_2) ; also on sheet 4
PEX_NIC2_TXN8: C1294.1 ; also on sheet 4
PEX_NIC2_TXN8_C: C1294.2 J42.B5_1(RX0N_1)
PEX_NIC2_TXN9: C1309.1 ; also on sheet 4
PEX_NIC2_TXN9_C: C1309.2 J42.A5_1(RX1N_1)
PEX_NIC2_TXN10: C1282.1 ; also on sheet 4
PEX_NIC2_TXN10_C: C1282.2 J42.B8_1(RX2N_1)
PEX_NIC2_TXN11: C1285.1 ; also on sheet 4
PEX_NIC2_TXN11_C: C1285.2 J42.A8_1(RX3N_1)
PEX_NIC2_TXN12: C1271.1 ; also on sheet 4
PEX_NIC2_TXN12_C: C1271.2 J42.B5_2(RX0N_2)
PEX_NIC2_TXN13: C1270.1 ; also on sheet 4
PEX_NIC2_TXN13_C: C1270.2 J42.A5_2(RX1N_2)
PEX_NIC2_TXN14: C1302.1 ; also on sheet 4
PEX_NIC2_TXN14_C: C1302.2 J42.B8_2(RX2N_2)
PEX_NIC2_TXN15: C1291.1 ; also on sheet 4
PEX_NIC2_TXN15_C: C1291.2 J42.A8_2(RX3N_2)
PEX_NIC2_TXP8: C1290.1 ; also on sheet 4
PEX_NIC2_TXP8_C: C1290.2 J42.B4_1(RX0P_1)
PEX_NIC2_TXP9: C1303.1 ; also on sheet 4
PEX_NIC2_TXP9_C: C1303.2 J42.A4_1(RX1P_1)
PEX_NIC2_TXP10: C1295.1 ; also on sheet 4
PEX_NIC2_TXP10_C: C1295.2 J42.B7_1(RX2P_1)
PEX_NIC2_TXP11: C1277.1 ; also on sheet 4
PEX_NIC2_TXP11_C: C1277.2 J42.A7_1(RX3P_1)
PEX_NIC2_TXP12: C1287.1 ; also on sheet 4
PEX_NIC2_TXP12_C: C1287.2 J42.B4_2(RX0P_2)
PEX_NIC2_TXP13: C1280.1 ; also on sheet 4
PEX_NIC2_TXP13_C: C1280.2 J42.A4_2(RX1P_2)
PEX_NIC2_TXP14: C1284.1 ; also on sheet 4
PEX_NIC2_TXP14_C: C1284.2 J42.B7_2(RX2P_2)
PEX_NIC2_TXP15: C1305.1 ; also on sheet 4
PEX_NIC2_TXP15_C: C1305.2 J42.A7_2(RX3P_2)
PEX_NIC3_RXN0: J43.D5_1(TX0N_1) ; also on sheet 16
PEX_NIC3_RXN1: J43.C5_1(TX1N_1) ; also on sheet 16
PEX_NIC3_RXN2: J43.D8_1(TX2N_1) ; also on sheet 16
PEX_NIC3_RXN3: J43.C8_1(TX3N_1) ; also on sheet 16
PEX_NIC3_RXN4: J43.D5_2(TX0N_2) ; also on sheet 16
PEX_NIC3_RXN5: J43.C5_2(TX1N_2) ; also on sheet 16
PEX_NIC3_RXN6: J43.D8_2(TX2N_2) ; also on sheet 16
PEX_NIC3_RXN7: J43.C8_2(TX3N_2) ; also on sheet 16
PEX_NIC3_RXP0: J43.D4_1(TX0P_1) ; also on sheet 16
PEX_NIC3_RXP1: J43.C4_1(TX1P_1) ; also on sheet 16
PEX_NIC3_RXP2: J43.D7_1(TX2P_1) ; also on sheet 16
PEX_NIC3_RXP3: J43.C7_1(TX3P_1) ; also on sheet 16
PEX_NIC3_RXP4: J43.D4_2(TX0P_2) ; also on sheet 16
PEX_NIC3_RXP5: J43.C4_2(TX1P_2) ; also on sheet 16
PEX_NIC3_RXP6: J43.D7_2(TX2P_2) ; also on sheet 16
PEX_NIC3_RXP7: J43.C7_2(TX3P_2) ; also on sheet 16
PEX_NIC3_TXN0: C1340.1 ; also on sheet 16
PEX_NIC3_TXN0_C: C1340.2 J43.B5_1(RX0N_1)
PEX_NIC3_TXN1: C1310.1 ; also on sheet 16
PEX_NIC3_TXN1_C: C1310.2 J43.A5_1(RX1N_1)
PEX_NIC3_TXN2: C1333.1 ; also on sheet 16
PEX_NIC3_TXN2_C: C1333.2 J43.B8_1(RX2N_1)
PEX_NIC3_TXN3: C1316.1 ; also on sheet 16
PEX_NIC3_TXN3_C: C1316.2 J43.A8_1(RX3N_1)
PEX_NIC3_TXN4: C1314.1 ; also on sheet 16
PEX_NIC3_TXN4_C: C1314.2 J43.B5_2(RX0N_2)
PEX_NIC3_TXN5: C1337.1 ; also on sheet 16
PEX_NIC3_TXN5_C: C1337.2 J43.A5_2(RX1N_2)
PEX_NIC3_TXN6: C1325.1 ; also on sheet 16
PEX_NIC3_TXN6_C: C1325.2 J43.B8_2(RX2N_2)
PEX_NIC3_TXN7: C1335.1 ; also on sheet 16
PEX_NIC3_TXN7_C: C1335.2 J43.A8_2(RX3N_2)
PEX_NIC3_TXP0: C1329.1 ; also on sheet 16
PEX_NIC3_TXP0_C: C1329.2 J43.B4_1(RX0P_1)
PEX_NIC3_TXP1: C1319.1 ; also on sheet 16
PEX_NIC3_TXP1_C: C1319.2 J43.A4_1(RX1P_1)
PEX_NIC3_TXP2: C1338.1 ; also on sheet 16
PEX_NIC3_TXP2_C: C1338.2 J43.B7_1(RX2P_1)
PEX_NIC3_TXP3: C1317.1 ; also on sheet 16
PEX_NIC3_TXP3_C: C1317.2 J43.A7_1(RX3P_1)
PEX_NIC3_TXP4: C1331.1 ; also on sheet 16
PEX_NIC3_TXP4_C: C1331.2 J43.B4_2(RX0P_2)
PEX_NIC3_TXP5: C1322.1 ; also on sheet 16
PEX_NIC3_TXP5_C: C1322.2 J43.A4_2(RX1P_2)
PEX_NIC3_TXP6: C1326.1 ; also on sheet 16
PEX_NIC3_TXP6_C: C1326.2 J43.B7_2(RX2P_2)
PEX_NIC3_TXP7: C1313.1 ; also on sheet 16
PEX_NIC3_TXP7_C: C1313.2 J43.A7_2(RX3P_2)
PEX_NIC4_RXN8: J45.D5_1(TX0N_1) ; also on sheet 16
PEX_NIC4_RXN9: J45.C5_1(TX1N_1) ; also on sheet 16
PEX_NIC4_RXN10: J45.D8_1(TX2N_1) ; also on sheet 16
PEX_NIC4_RXN11: J45.C8_1(TX3N_1) ; also on sheet 16
PEX_NIC4_RXN12: J45.D5_2(TX0N_2) ; also on sheet 16
PEX_NIC4_RXN13: J45.C5_2(TX1N_2) ; also on sheet 16
PEX_NIC4_RXN14: J45.D8_2(TX2N_2) ; also on sheet 16
PEX_NIC4_RXN15: J45.C8_2(TX3N_2) ; also on sheet 16
PEX_NIC4_RXP8: J45.D4_1(TX0P_1) ; also on sheet 16
PEX_NIC4_RXP9: J45.C4_1(TX1P_1) ; also on sheet 16
PEX_NIC4_RXP10: J45.D7_1(TX2P_1) ; also on sheet 16
PEX_NIC4_RXP11: J45.C7_1(TX3P_1) ; also on sheet 16
PEX_NIC4_RXP12: J45.D4_2(TX0P_2) ; also on sheet 16
PEX_NIC4_RXP13: J45.C4_2(TX1P_2) ; also on sheet 16
PEX_NIC4_RXP14: J45.D7_2(TX2P_2) ; also on sheet 16
PEX_NIC4_RXP15: J45.C7_2(TX3P_2) ; also on sheet 16
PEX_NIC4_TXN8: C1330.1 ; also on sheet 16
PEX_NIC4_TXN8_C: C1330.2 J45.B5_1(RX0N_1)
PEX_NIC4_TXN9: C1341.1 ; also on sheet 16
PEX_NIC4_TXN9_C: C1341.2 J45.A5_1(RX1N_1)
PEX_NIC4_TXN10: C1320.1 ; also on sheet 16
PEX_NIC4_TXN10_C: C1320.2 J45.B8_1(RX2N_1)
PEX_NIC4_TXN11: C1323.1 ; also on sheet 16
PEX_NIC4_TXN11_C: C1323.2 J45.A8_1(RX3N_1)
PEX_NIC4_TXN12: C1311.1 ; also on sheet 16
PEX_NIC4_TXN12_C: C1311.2 J45.B5_2(RX0N_2)
PEX_NIC4_TXN13: C1312.1 ; also on sheet 16
PEX_NIC4_TXN13_C: C1312.2 J45.A5_2(RX1N_2)
PEX_NIC4_TXN14: C1334.1 ; also on sheet 16
PEX_NIC4_TXN14_C: C1334.2 J45.B8_2(RX2N_2)
PEX_NIC4_TXN15: C1328.1 ; also on sheet 16
PEX_NIC4_TXN15_C: C1328.2 J45.A8_2(RX3N_2)
PEX_NIC4_TXP8: C1327.1 ; also on sheet 16
PEX_NIC4_TXP8_C: C1327.2 J45.B4_1(RX0P_1)
PEX_NIC4_TXP9: C1336.1 ; also on sheet 16
PEX_NIC4_TXP9_C: C1336.2 J45.A4_1(RX1P_1)
PEX_NIC4_TXP10: C1332.1 ; also on sheet 16
PEX_NIC4_TXP10_C: C1332.2 J45.B7_1(RX2P_1)
PEX_NIC4_TXP11: C1315.1 ; also on sheet 16
PEX_NIC4_TXP11_C: C1315.2 J45.A7_1(RX3P_1)
PEX_NIC4_TXP12: C1324.1 ; also on sheet 16
PEX_NIC4_TXP12_C: C1324.2 J45.B4_2(RX0P_2)
PEX_NIC4_TXP13: C1318.1 ; also on sheet 16
PEX_NIC4_TXP13_C: C1318.2 J45.A4_2(RX1P_2)
PEX_NIC4_TXP14: C1321.1 ; also on sheet 16
PEX_NIC4_TXP14_C: C1321.2 J45.B7_2(RX2P_2)
PEX_NIC4_TXP15: C1339.1 ; also on sheet 16
PEX_NIC4_TXP15_C: C1339.2 J45.A7_2(RX3P_2)
PEX_PE7_RXN0: J10.A17(HSIP0-) ; also on sheet 18
PEX_PE7_RXN1: J10.A22(HSIP1-) ; also on sheet 18
PEX_PE7_RXN2: J10.A26(HSIP2-) ; also on sheet 18
PEX_PE7_RXN3: J10.A30(HSIP3-) ; also on sheet 18
PEX_PE7_RXN4: J10.A36(HSIP4-) ; also on sheet 18
PEX_PE7_RXN5: J10.A40(HSIP5-) ; also on sheet 18
PEX_PE7_RXN6: J10.A44(HSIP6-) ; also on sheet 18
PEX_PE7_RXN7: J10.A48(HSIP7-) ; also on sheet 18
PEX_PE7_RXN8: J10.A53(HSIP8-) ; also on sheet 18
PEX_PE7_RXN9: J10.A57(HSIP9-) ; also on sheet 18
PEX_PE7_RXN10: J10.A61(HSIP10-) ; also on sheet 18
PEX_PE7_RXN11: J10.A65(HSIP11-) ; also on sheet 18
PEX_PE7_RXN12: J10.A69(HSIP12-) ; also on sheet 18
PEX_PE7_RXN13: J10.A73(HSIP13-) ; also on sheet 18
PEX_PE7_RXN14: J10.A77(HSIP14-) ; also on sheet 18
PEX_PE7_RXN15: J10.A81(HSIP15-) ; also on sheet 18
PEX_PE7_RXP0: J10.A16(HSIP0+) ; also on sheet 18
PEX_PE7_RXP1: J10.A21(HSIP1+) ; also on sheet 18
PEX_PE7_RXP2: J10.A25(HSIP2+) ; also on sheet 18
PEX_PE7_RXP3: J10.A29(HSIP3+) ; also on sheet 18
PEX_PE7_RXP4: J10.A35(HSIP4+) ; also on sheet 18
PEX_PE7_RXP5: J10.A39(HSIP5+) ; also on sheet 18
PEX_PE7_RXP6: J10.A43(HSIP6+) ; also on sheet 18
PEX_PE7_RXP7: J10.A47(HSIP7+) ; also on sheet 18
PEX_PE7_RXP8: J10.A52(HSIP8+) ; also on sheet 18
PEX_PE7_RXP9: J10.A56(HSIP9+) ; also on sheet 18
PEX_PE7_RXP10: J10.A60(HSIP10+) ; also on sheet 18
PEX_PE7_RXP11: J10.A64(HSIP11+) ; also on sheet 18
PEX_PE7_RXP12: J10.A68(HSIP12+) ; also on sheet 18
PEX_PE7_RXP13: J10.A72(HSIP13+) ; also on sheet 18
PEX_PE7_RXP14: J10.A76(HSIP14) ; also on sheet 18
PEX_PE7_RXP15: J10.A80(HSIP15+) ; also on sheet 18
PEX_PE7_TXN0: C835.1 ; also on sheet 18
PEX_PE7_TXN0_C: C835.2 J10.B15(HSOP0-)
PEX_PE7_TXN1: C837.1 ; also on sheet 18
PEX_PE7_TXN1_C: C837.2 J10.B20(HSOP1-)
PEX_PE7_TXN2: C839.1 ; also on sheet 18
PEX_PE7_TXN2_C: C839.2 J10.B24(HSOP2-)
PEX_PE7_TXN3: C841.1 ; also on sheet 18
PEX_PE7_TXN3_C: C841.2 J10.B28(HSOP3-)
PEX_PE7_TXN4: C843.1 ; also on sheet 18
PEX_PE7_TXN4_C: C843.2 J10.B34(HSOP4-)
PEX_PE7_TXN5: C845.1 ; also on sheet 18
PEX_PE7_TXN5_C: C845.2 J10.B38(HSOP5-)
PEX_PE7_TXN6: C847.1 ; also on sheet 18
PEX_PE7_TXN6_C: C847.2 J10.B42(HSOP6-)
PEX_PE7_TXN7: C849.1 ; also on sheet 18
PEX_PE7_TXN7_C: C849.2 J10.B46(HSOP7-)
PEX_PE7_TXN8: C851.1 ; also on sheet 18
PEX_PE7_TXN8_C: C851.2 J10.B51(HSOP8-)
PEX_PE7_TXN9: C853.1 ; also on sheet 18
PEX_PE7_TXN9_C: C853.2 J10.B55(HSOP9-)
PEX_PE7_TXN10: C855.1 ; also on sheet 18
PEX_PE7_TXN10_C: C855.2 J10.B59(HSOP10-)
PEX_PE7_TXN11: C857.1 ; also on sheet 18
PEX_PE7_TXN11_C: C857.2 J10.B63(HSOP11-)
PEX_PE7_TXN12: C859.1 ; also on sheet 18
PEX_PE7_TXN12_C: C859.2 J10.B67(HSOP12-)
PEX_PE7_TXN13: C861.1 ; also on sheet 18
PEX_PE7_TXN13_C: C861.2 J10.B71(HSOP13-)
PEX_PE7_TXN14: C863.1 ; also on sheet 18
PEX_PE7_TXN14_C: C863.2 J10.B75(HSOP14-)
PEX_PE7_TXN15: C865.1 ; also on sheet 18
PEX_PE7_TXN15_C: C865.2 J10.B79(HSOP15-)
PEX_PE7_TXP0: C834.1 ; also on sheet 18
PEX_PE7_TXP0_C: C834.2 J10.B14(HSOP0+)
PEX_PE7_TXP1: C836.1 ; also on sheet 18
PEX_PE7_TXP1_C: C836.2 J10.B19(HSOP1+)
PEX_PE7_TXP2: C838.1 ; also on sheet 18
PEX_PE7_TXP2_C: C838.2 J10.B23(HSOP2+)
PEX_PE7_TXP3: C840.1 ; also on sheet 18
PEX_PE7_TXP3_C: C840.2 J10.B27(HSOP3+)
PEX_PE7_TXP4: C842.1 ; also on sheet 18
PEX_PE7_TXP4_C: C842.2 J10.B33(HSOP4+)
PEX_PE7_TXP5: C844.1 ; also on sheet 18
PEX_PE7_TXP5_C: C844.2 J10.B37(HSOP5+)
PEX_PE7_TXP6: C846.1 ; also on sheet 18
PEX_PE7_TXP6_C: C846.2 J10.B41(HSOP6+)
PEX_PE7_TXP7: C848.1 ; also on sheet 18
PEX_PE7_TXP7_C: C848.2 J10.B45(HSOP7+)
PEX_PE7_TXP8: C850.1 ; also on sheet 18
PEX_PE7_TXP8_C: C850.2 J10.B50(HSOP8+)
PEX_PE7_TXP9: C852.1 ; also on sheet 18
PEX_PE7_TXP9_C: C852.2 J10.B54(HSOP9+)
PEX_PE7_TXP10: C854.1 ; also on sheet 18
PEX_PE7_TXP10_C: C854.2 J10.B58(HSOP10+)
PEX_PE7_TXP11: C856.1 ; also on sheet 18
PEX_PE7_TXP11_C: C856.2 J10.B62(HSOP11+)
PEX_PE7_TXP12: C858.1 ; also on sheet 18
PEX_PE7_TXP12_C: C858.2 J10.B66(HSOP12+)
PEX_PE7_TXP13: C860.1 ; also on sheet 18
PEX_PE7_TXP13_C: C860.2 J10.B70(HSOP13+)
PEX_PE7_TXP14: C862.1 ; also on sheet 18
PEX_PE7_TXP14_C: C862.2 J10.B74(HSOP14+)
PEX_PE7_TXP15: C864.1 ; also on sheet 18
PEX_PE7_TXP15_C: C864.2 J10.B78(HSOP15+)
PMBUS_ALERT_N: R589.2 ; also on sheet 48 49 50
PMBUS_ALERT_RC_N: C900.1 J28.3 R588.2 R589.1
PMBUS_CLK: J28.1 R586.2 U77.6(SCL2)
PMBUS_DAT: J28.2 R587.2 U77.5(SDA2)
PMBUS_HSC_BUF_CLK: R591.2 U77.3(SCL1) ; also on sheet 48 49 50
PMBUS_HSC_BUF_DAT: R590.2 U77.4(SDA1) ; also on sheet 48 49 50
PU_PMBUS_HSC_BUF_EN: R592.2 U77.8(EN)
PU_SMB_PLX1_PCA9306_EN: R649.2 U10.7(VREF2) U10.8(EN)
PU_SMB_PLX2_PCA9306_EN: R656.2 U11.7(VREF2) U11.8(EN)
PWRGD_P3V3: J11.8(PWR_OK) ; also on sheet 59 60 61
RES: J11.20(RES)
RST_MUX1_N: R619.1 ; also on sheet 55
RST_MUX2_N: R640.1 ; also on sheet 55
RST_MUX3_N: R1119.1 ; also on sheet 55
RST_MUX_PCA9548_A_N: R619.2 U8.3(RESET#)
RST_MUX_PCA9548_B_N: R640.2 U9.3(RESET#)
RST_MUX_PCA9548_C_N: R1119.2 U105.3(RESET#)
RST_NIC1_N: R1154.1 ; also on sheet 54
RST_NIC1_R_N: J41.B1_2(Vact_B_2) R1154.2
RST_NIC2_N: R1155.1 ; also on sheet 54
RST_NIC2_R_N: J42.B1_2(Vact_B_2) R1155.2
RST_NIC3_N: R1156.1 ; also on sheet 54
RST_NIC3_R_N: J43.B1_2(Vact_B_2) R1156.2
RST_NIC4_N: R1157.1 ; also on sheet 54
RST_NIC4_R_N: J45.B1_2(Vact_B_2) R1157.2
RST_PCIE_SLOT_7_N: R575.2 ; also on sheet 54
RST_PCIE_SLOT_7_R_N: J10.A11(PERST#) R575.1
SMB_CLKGEN_B_SCL: R1071.2 U9.16(SC5) ; also on sheet 28
SMB_CLKGEN_B_SDA: R1072.2 U9.15(SD5) ; also on sheet 28
SMB_CLKGEN_SCL: R632.2 U9.9(SC2) ; also on sheet 27
SMB_CLKGEN_SDA: R633.2 U9.8(SD2) ; also on sheet 27
SMB_EEPROM_SCL: R636.2 R775.1 R845.1 R890.1 U9.14(SC4)
SMB_EEPROM_SCL_R: R845.2 R848.2 U17.2(SCL)
SMB_EEPROM_SDA: R637.2 R776.1 R846.1 R891.1 U9.13(SD4)
SMB_EEPROM_SDA_R: R846.2 R847.2 U17.1(SDA)
SMB_FRU_SCL_R: R767.2 R775.2 U18.6(SCL)
SMB_FRU_SDA_R: R768.2 R776.2 U18.5(SDA)
SMB_HDD_BP1_SCL: J29.3 R597.2 R628.2 U9.5(SC0)
SMB_HDD_BP1_SDA: J29.1 R598.2 R629.2 U9.4(SD0)
SMB_HWMON_SCL: R634.2 U9.11(SC3) ; also on sheet 51
SMB_HWMON_SDA: R635.2 U9.10(SD3) ; also on sheet 51
SMB_IPMB_5VSB_CLK: J27.3 R579.2 R617.1 R638.1 R1121.1
SMB_IPMB_5VSB_DAT: J27.1 R580.2 R618.1 R639.1 R1120.1
SMB_NIC1_SCL: R1078.2 R1124.2 U105.5(SC0)
SMB_NIC1_SCL_R: J41.C1_2(SCL_2) R1078.1 R1081.1
SMB_NIC1_SDA: R1077.2 R1125.2 U105.4(SD0)
SMB_NIC1_SDA_R: J41.C2_2(SDA_2) R1073.1 R1077.1
SMB_NIC2_SCL: R1079.2 R1126.2 U105.7(SC1)
SMB_NIC2_SCL_R: J42.C1_2(SCL_2) R1079.1 R1083.1
SMB_NIC2_SDA: R1080.2 R1127.2 U105.6(SD1)
SMB_NIC2_SDA_R: J42.C2_2(SDA_2) R1080.1 R1082.1
SMB_NIC3_SCL: R1084.2 R1129.2 U105.9(SC2)
SMB_NIC3_SCL_R: J43.C1_2(SCL_2) R1084.1 R1089.1
SMB_NIC3_SDA: R1085.2 R1128.2 U105.8(SD2)
SMB_NIC3_SDA_R: J43.C2_2(SDA_2) R1085.1 R1088.1
SMB_NIC4_SCL: R1086.2 R1130.2 U105.11(SC3)
SMB_NIC4_SCL_R: J45.C1_2(SCL_2) R1086.1 R1091.1
SMB_NIC4_SDA: R1087.2 R1131.2 U105.10(SD3)
SMB_NIC4_SDA_R: J45.C2_2(SDA_2) R1087.1 R1090.1
SMB_PCA9548_A_SCL: R599.2 R617.2 U8.22(SCL)
SMB_PCA9548_A_SDA: R600.2 R618.2 U8.23(SDA)
SMB_PCA9548_B_SCL: R626.2 R638.2 U9.22(SCL)
SMB_PCA9548_B_SDA: R627.2 R639.2 U9.23(SDA)
SMB_PCA9548_C_SCL: R1121.2 R1122.2 U105.22(SCL)
SMB_PCA9548_C_SDA: R1120.2 R1123.2 U105.23(SDA)
SMB_PE0_SCL: R601.2 U8.5(SC0) ; also on sheet 31
SMB_PE0_SDA: R602.2 U8.4(SD0) ; also on sheet 31
SMB_PE1_SCL: R603.2 U8.7(SC1) ; also on sheet 32
SMB_PE1_SDA: R604.2 U8.6(SD1) ; also on sheet 32
SMB_PE2_SCL: R605.2 U8.9(SC2) ; also on sheet 33
SMB_PE2_SDA: R606.2 U8.8(SD2) ; also on sheet 33
SMB_PE3_SCL: R607.2 U8.11(SC3) ; also on sheet 34
SMB_PE3_SDA: R608.2 U8.10(SD3) ; also on sheet 34
SMB_PE4_SCL: R609.2 U8.14(SC4) ; also on sheet 35
SMB_PE4_SDA: R610.2 U8.13(SD4) ; also on sheet 35
SMB_PE5_SCL: R611.2 U8.16(SC5) ; also on sheet 36
SMB_PE5_SDA: R612.2 U8.15(SD5) ; also on sheet 36
SMB_PE6_SCL: R613.2 U8.18(SC6) ; also on sheet 37
SMB_PE6_SDA: R614.2 U8.17(SD6) ; also on sheet 37
SMB_PE7_SCL: R572.1 R615.2 U8.20(SC7)
SMB_PE7_SCL_R: J10.B5(SMCLK) R569.2 R572.2
SMB_PE7_SDA: R573.1 R616.2 U8.19(SD7)
SMB_PE7_SDA_R: J10.B6(SMDATA) R570.2 R573.2
SMB_PLX1_PCA9306_SCL_R: JP2.1 R648.2 R653.2 U10.6(SCL2)
SMB_PLX1_PCA9306_SDA_R: JP2.3 R647.2 R652.2 U10.5(SDA2)
SMB_PLX1_SCL: R651.2 U10.3(SCL1) ; also on sheet 9
SMB_PLX1_SDA: R650.2 U10.4(SDA1) ; also on sheet 9
SMB_PLX2_PCA9306_SCL_R: JP3.1 R655.2 R660.2 U11.6(SCL2)
SMB_PLX2_PCA9306_SDA_R: JP3.3 R654.2 R659.2 U11.5(SDA2)
SMB_PLX2_SCL: R658.2 U11.3(SCL1) ; also on sheet 21
SMB_PLX2_SDA: R657.2 U11.4(SDA1) ; also on sheet 21
SMB_PLX_PCA9306_SCL: R630.2 R653.1 R660.1 U9.7(SC1)
SMB_PLX_PCA9306_SDA: R631.2 R652.1 R659.1 U9.6(SD1)
SMB_TMPE_SCL_R: R890.2 R893.2 U102.2(SCL)
SMB_TMPE_SDA_R: R891.2 R892.2 U102.1(SDA)
TP_IRQ_FAN_12V_GATE: J27.5
TP_NIC1_SMBUS_ALERT_N: J41.D2_2(Vman_2)
TP_NIC1_WAKE_N: J41.D1_2(Vact_D_2)
TP_NIC2_SMBUS_ALERT_N: J42.D2_2(Vman_2)
TP_NIC2_WAKE_N: J42.D1_2(Vact_D_2)
TP_NIC3_SMBUS_ALERT_N: J43.D2_2(Vman_2)
TP_NIC3_WAKE_N: J43.D1_2(Vact_D_2)
TP_NIC4_SMBUS_ALERT_N: J45.D2_2(Vman_2)
TP_NIC4_WAKE_N: J45.D1_2(Vact_D_2)
TP_P3V3_MB: J27.7
TP_P5V_MB: J27.6
TP_P5V_STBY: J27.4
TP_PE_SLOT7_JTAG_TDO: J10.A7(JTAG4)
TP_PE_SLOT7_RSVD_B82: J10.B82(RSVD3)
TP_SLOT7_JTAG_TCK: J10.A5(JTAG2)
TP_SLOT7_JTAG_TDI: J10.A6(JTAG3)
TP_SLOT7_JTAG_TMS: J10.A8(JTAG5)
TP_SLOT7_JTAG_TRST_N: J10.B9(JTAG1)
TP_SLOT7_RSVD_A19: J10.A19(RSVD4)
TP_SLOT7_RSVD_A32: J10.A32(RSVD5)
TP_SLOT7_RSVD_A33: J10.A33(RSVD6)
TP_SLOT7_RSVD_A50: J10.A50(RSVD7)
TP_SLOT7_RSVD_B30: J10.B30(RSVD2)
TP_SLOT7_WAKE_N: J10.B11(WAKE_N)

Not connected (* = marked no-connect by the designer): J41 A1_1(Reserved_1) A2_1(IntL_1) B1_1(Vact_B_1) B2_1(ModPrsL_1) C2_1(SDA_1) D1_1(Vact_D_1) D2_1(Vman_1); J42 A1_1(Reserved_1) A2_1(IntL_1) B1_1(Vact_B_1) B2_1(ModPrsL_1) C1_1(SCL_1) C2_1(SDA_1) D1_1(Vact_D_1) D2_1(Vman_1); J43 A1_1(Reserved_1) A2_1(IntL_1) B1_1(Vact_B_1) B2_1(ModPrsL_1) C2_1(SDA_1) D1_1(Vact_D_1) D2_1(Vman_1); J45 A1_1(Reserved_1) A2_1(IntL_1) B1_1(Vact_B_1) B2_1(ModPrsL_1) C1_1(SCL_1) C2_1(SDA_1) D1_1(Vact_D_1) D2_1(Vman_1); U17 3(ALERT)*; U28 8(IMON)* 9(FLTB)*; U102 3(ALERT)*

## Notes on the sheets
sheet 47
- 5x6
